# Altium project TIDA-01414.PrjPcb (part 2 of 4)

## Sheet TIDA-01414_UpChannel.SchDoc: Main Schematic
size 538 x 342 mm; Date: Not shown in title block; ApprovedBy: Not shown in title block; CheckedBy: Not shown in title block; Author: Not shown in title block; CompanyName: Not shown in title block; DrawnBy: LDN; Engineer: Not shown in title block; Organization: Not shown in title block; Address1: Not shown in title block; Address2: Not shown in title block; Address3: Not shown in title block; Address4: Not shown in title block; DocumentNumber: 4; Revision: Use project parameter SCH_Rev; SheetNumber: 4; SheetTotal: 12; PageSetup: Record=PageOptions¦CenterHorizontal=True¦CenterVertical=True¦PrintScale=1.00¦XCorrection=1.00¦YCorrection=1.00¦PrintKind=0¦BorderSize=5000000¦LeftOffset=0¦BottomOffset=0¦Orientation=2¦PaperLength=1000¦PaperWidth=1000¦Scale=100¦PaperSource=15¦PrintQuality=600¦MediaType=1¦DitherType=10¦PaperKind=Letter¦PrintScaleMode=1
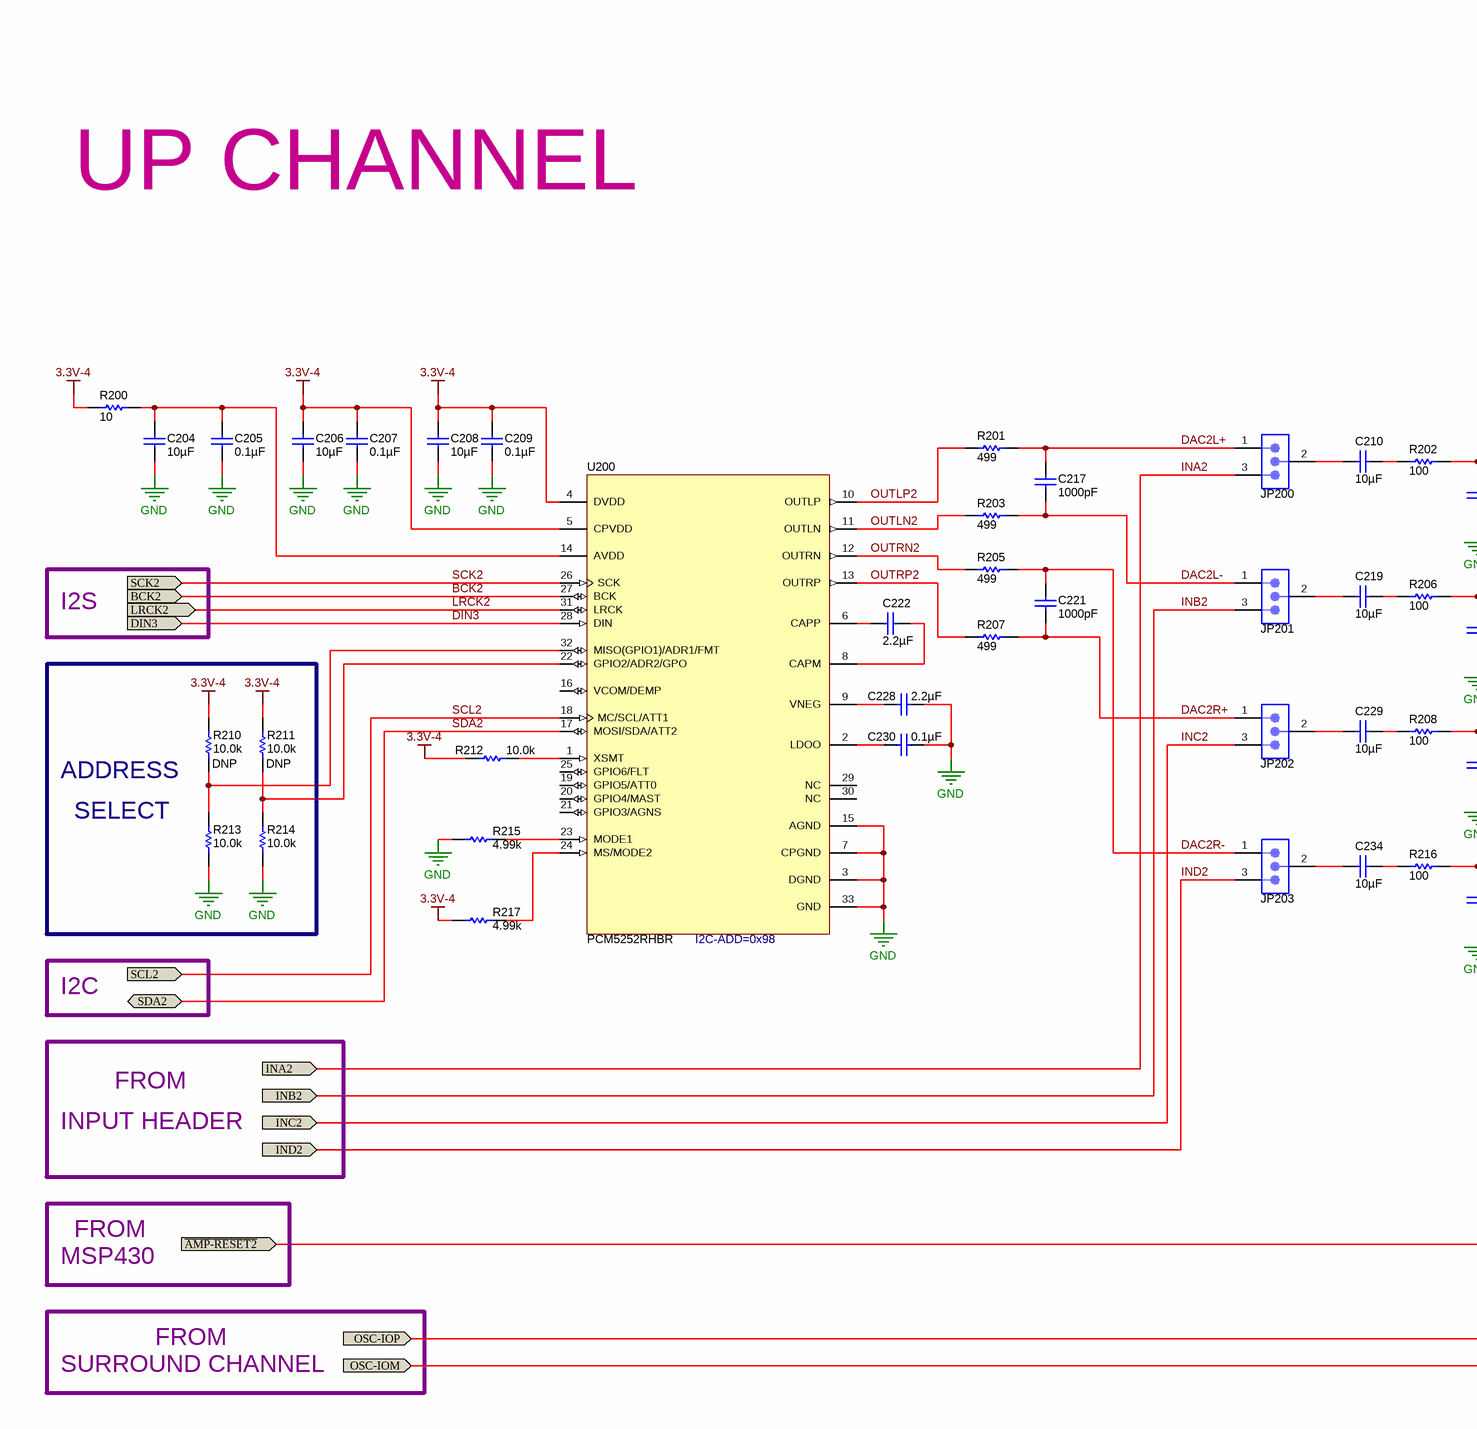
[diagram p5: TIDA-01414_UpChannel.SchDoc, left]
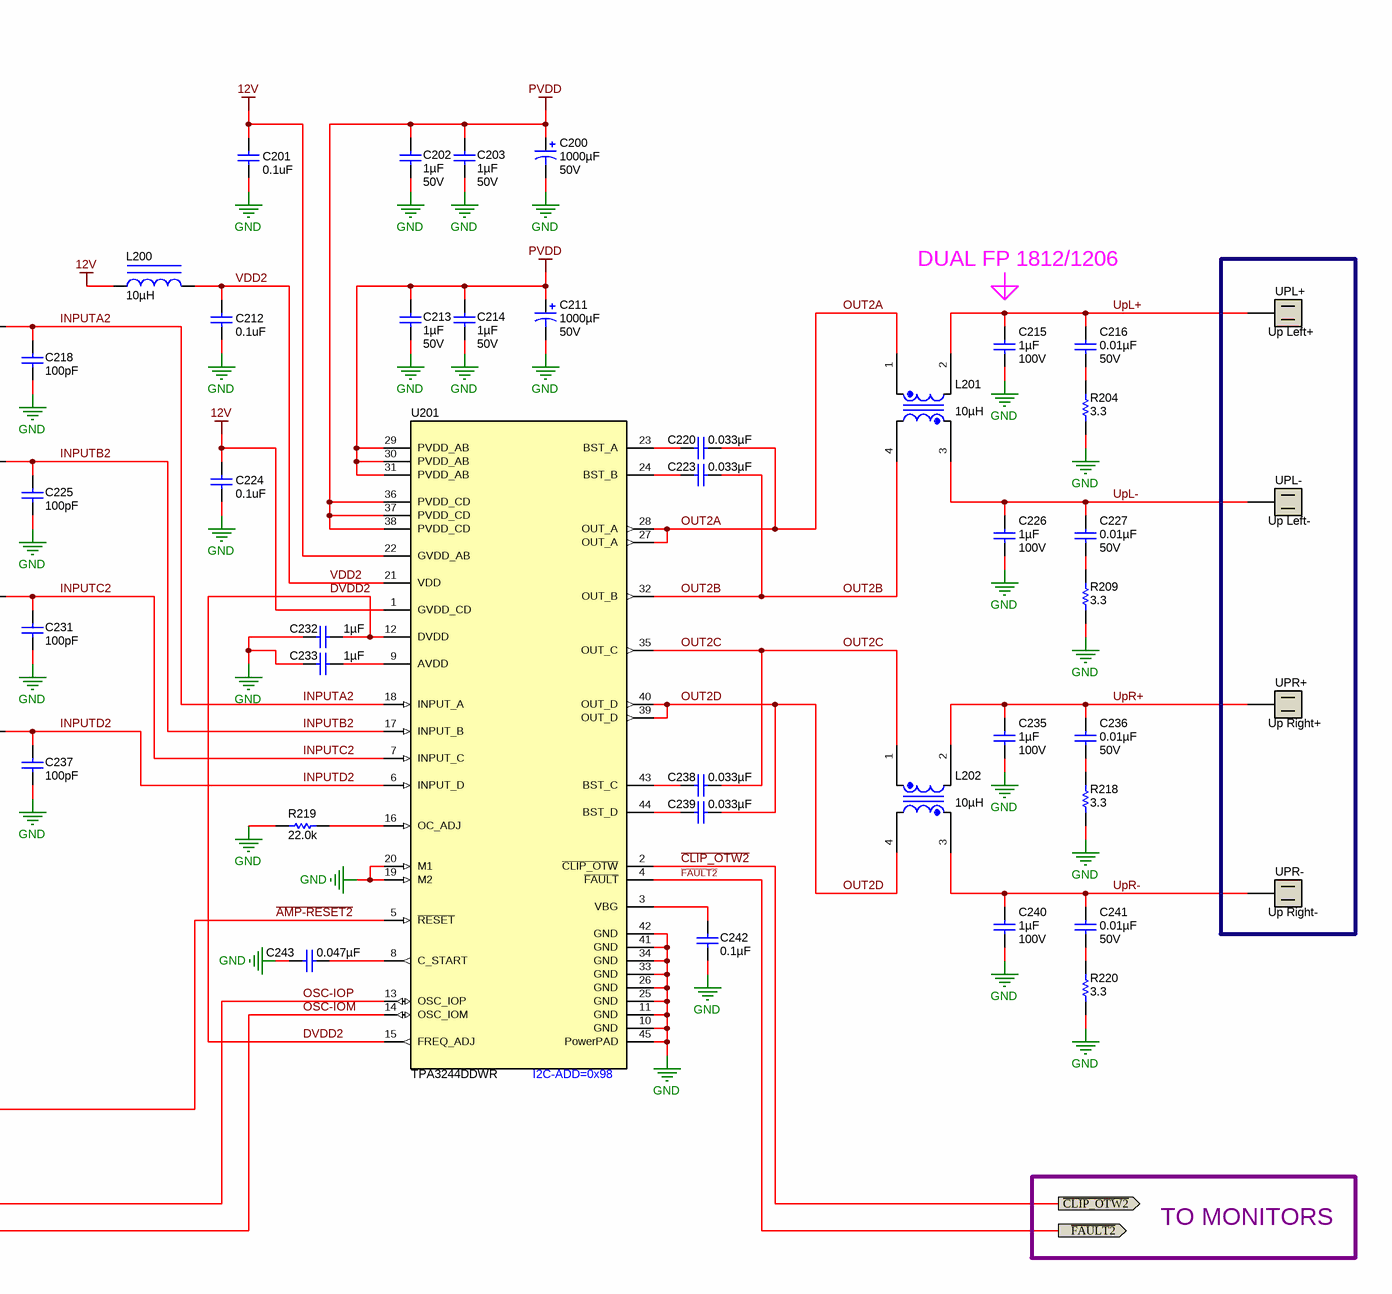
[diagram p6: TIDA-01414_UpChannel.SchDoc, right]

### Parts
C200  ValueDisplayed: 1000µF  Value2: 50V  [SM_RADIAL_J16]  (hidden comment: +)
C201  value 0.1uF  [0603L]  (hidden comment: C0603C104K5RACTU)
C202  ValueDisplayed: 1µF  Value2: 50V  [1206L]  (hidden comment: GRM31MR71H105KA88L)
C203  ValueDisplayed: 1µF  Value2: 50V  [1206L]  (hidden comment: GRM31MR71H105KA88L)
C204  ValueDisplayed: 10µF  [0603L]  (hidden comment: GRM188R61A106ME69D)
C205  ValueDisplayed: 0.1µF  [0402L]  (hidden comment: GRM155R71A104KA01D)
C206  ValueDisplayed: 10µF  [0603L]  (hidden comment: GRM188R61A106ME69D)
C207  ValueDisplayed: 0.1µF  [0402L]  (hidden comment: GRM155R71A104KA01D)
C208  ValueDisplayed: 10µF  [0603L]  (hidden comment: GRM188R61A106ME69D)
C209  ValueDisplayed: 0.1µF  [0402L]  (hidden comment: GRM155R71A104KA01D)
C210  ValueDisplayed: 10µF  [1206_180]  (hidden comment: GRM31CR71C106KAC7L)
C211  ValueDisplayed: 1000µF  Value2: 50V  [SM_RADIAL_J16]  (hidden comment: +)
C212  value 0.1uF  [0603L]  (hidden comment: C0603C104K5RACTU)
C213  ValueDisplayed: 1µF  Value2: 50V  [1206L]  (hidden comment: GRM31MR71H105KA88L)
C214  ValueDisplayed: 1µF  Value2: 50V  [1206L]  (hidden comment: GRM31MR71H105KA88L)
C215  ValueDisplayed: 1µF  Value2: 100V  [1210_220]  (hidden comment: C3225X7R2A105K200AA)
C216  ValueDisplayed: 0.01µF  Value2: 50V  [0603L]  (hidden comment: C0603C103K5RACTU)
C217  ValueDisplayed: 1000pF  [0402L]  (hidden comment: GRM1555C1H102JA01D)
C218  ValueDisplayed: 100pF  [0603L]  (hidden comment: GRM1885C1H101JA01D)
C219  ValueDisplayed: 10µF  [1206_180]  (hidden comment: GRM31CR71C106KAC7L)
C220  ValueDisplayed: 0.033µF  [0603L]  (hidden comment: GRM188R71E333KA01D)
C221  ValueDisplayed: 1000pF  [0402L]  (hidden comment: GRM1555C1H102JA01D)
C222  ValueDisplayed: 2.2µF  [0402L]  (hidden comment: C1005X5R1A225K050BC)
C223  ValueDisplayed: 0.033µF  [0603L]  (hidden comment: GRM188R71E333KA01D)
C224  value 0.1uF  [0603L]  (hidden comment: C0603C104K5RACTU)
C225  ValueDisplayed: 100pF  [0603L]  (hidden comment: GRM1885C1H101JA01D)
C226  ValueDisplayed: 1µF  Value2: 100V  [1210_220]  (hidden comment: C3225X7R2A105K200AA)
C227  ValueDisplayed: 0.01µF  Value2: 50V  [0603L]  (hidden comment: C0603C103K5RACTU)
C228  ValueDisplayed: 2.2µF  [0402L]  (hidden comment: C1005X5R1A225K050BC)
C229  ValueDisplayed: 10µF  [1206_180]  (hidden comment: GRM31CR71C106KAC7L)
C230  ValueDisplayed: 0.1µF  [0402L]  (hidden comment: GRM155R71A104KA01D)
C231  ValueDisplayed: 100pF  [0603L]  (hidden comment: GRM1885C1H101JA01D)
C232  ValueDisplayed: 1µF  [0603L]  (hidden comment: GRM188R71C105KA12D)
C233  ValueDisplayed: 1µF  [0603L]  (hidden comment: GRM188R71C105KA12D)
C234  ValueDisplayed: 10µF  [1206_180]  (hidden comment: GRM31CR71C106KAC7L)
C235  ValueDisplayed: 1µF  Value2: 100V  [1210_220]  (hidden comment: C3225X7R2A105K200AA)
C236  ValueDisplayed: 0.01µF  Value2: 50V  [0603L]  (hidden comment: C0603C103K5RACTU)
C237  ValueDisplayed: 100pF  [0603L]  (hidden comment: GRM1885C1H101JA01D)
C238  ValueDisplayed: 0.033µF  [0603L]  (hidden comment: GRM188R71E333KA01D)
C239  ValueDisplayed: 0.033µF  [0603L]  (hidden comment: GRM188R71E333KA01D)
C240  ValueDisplayed: 1µF  Value2: 100V  [1210_220]  (hidden comment: C3225X7R2A105K200AA)
C241  ValueDisplayed: 0.01µF  Value2: 50V  [0603L]  (hidden comment: C0603C103K5RACTU)
C242  ValueDisplayed: 0.1µF  [0603L]  (hidden comment: C0603C104K5RACTU)
C243  ValueDisplayed: 0.047µF  [0603L]  (hidden comment: GRM188R71H473KA61D)
JP200  PBC03SAAN  [PBC03SAAN]  (value not drawn)
JP201  PBC03SAAN  [PBC03SAAN]  (value not drawn)
JP202  PBC03SAAN  [PBC03SAAN]  (value not drawn)
JP203  PBC03SAAN  [PBC03SAAN]  (value not drawn)
L200  ValueDisplayed: 10µH  [0603L]  (hidden comment: GLFR1608T100M-LR)
L201  ValueDisplayed: 10µH  [Coilcraft_RA7231-ALB]  (hidden comment: UA8014-ALD)
L202  ValueDisplayed: 10µH  [Coilcraft_RA7231-ALB]  (hidden comment: UA8014-ALD)
R200  ValueDisplayed: 10  [0603L]  (hidden comment: CRCW060310R0JNEA)
R201  ValueDisplayed: 499  [0603L]  (hidden comment: CRCW0603499RFKEA)
R202  ValueDisplayed: 100  [0603L]  (hidden comment: CRCW0603100RFKEA)
R203  ValueDisplayed: 499  [0603L]  (hidden comment: CRCW0603499RFKEA)
R204  ValueDisplayed: 3.3  [0603L]  (hidden comment: CRCW06033R30JNEA)
R205  ValueDisplayed: 499  [0603L]  (hidden comment: CRCW0603499RFKEA)
R206  ValueDisplayed: 100  [0603L]  (hidden comment: CRCW0603100RFKEA)
R207  ValueDisplayed: 499  [0603L]  (hidden comment: CRCW0603499RFKEA)
R208  ValueDisplayed: 100  [0603L]  (hidden comment: CRCW0603100RFKEA)
R209  ValueDisplayed: 3.3  [0603L]  (hidden comment: CRCW06033R30JNEA)
R210  DNP  ValueDisplayed: 10.0k  [0402L]
R211  DNP  ValueDisplayed: 10.0k  [0402L]
R212  ValueDisplayed: 10.0k  [0402L]  (hidden comment: ERJ-2RKF1002X)
R213  ValueDisplayed: 10.0k  [0402L]  (hidden comment: ERJ-2RKF1002X)
R214  ValueDisplayed: 10.0k  [0402L]  (hidden comment: ERJ-2RKF1002X)
R215  ValueDisplayed: 4.99k  [0402L]  (hidden comment: CRCW04024K99FKED)
R216  ValueDisplayed: 100  [0603L]  (hidden comment: CRCW0603100RFKEA)
R217  ValueDisplayed: 4.99k  [0402L]  (hidden comment: CRCW04024K99FKED)
R218  ValueDisplayed: 3.3  [0603L]  (hidden comment: CRCW06033R30JNEA)
R219  ValueDisplayed: 22.0k  [0603L]  (hidden comment: RC0603FR-0722KL)
R220  ValueDisplayed: 3.3  [0603L]  (hidden comment: CRCW06033R30JNEA)
U200  PCM5252RHBR  [RHB0032E]
U201  TPA3244DDWR  [DDW0044D_N]
UPL+  Up Left+  [TEC-SpadeLug_63066-1]
UPL-  Up Left-  [TEC-SpadeLug_63066-1]
UPR+  Up Right+  [TEC-SpadeLug_63066-1]
UPR-  Up Right-  [TEC-SpadeLug_63066-1]

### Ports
BCK2 (in), DIN3 (in), INA2 (in), INB2 (in), INC2 (in), IND2 (in), LRCK2 (in), OSC-IOM (in), OSC-IOP (in), SCK2 (in), SCL2 (in), SDA2 (bidir), ~{AMP-RESET2} (in), ~{CLIP_OTW2} (out), ~{FAULT2} (out)

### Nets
3.3V-4: C206.1 C207.1 C208.1 C209.1 R200.1 R210.2 R211.2 R212.1 R217.2 U200.4(DVDD) U200.5(CPVDD)
12V: C201.1 C224.1 L200.1 U201.1(GVDD_CD) U201.22(GVDD_AB)
GND: C200.2(-) C201.2 C202.1 C203.1 C204.2 C205.2 C206.2 C207.2 C208.2 C209.2 C211.2(-) C212.2 C213.1 C214.1 C215.2 C218.2 C224.2 C225.2 C226.2 C228.2 C230.2 C231.2 C232.1 C233.1 C235.2 C237.2 C240.2 C242.1 C243.2 R204.1 R209.1 R213.1 R214.1 R215.2 R218.1 R219.1 R220.1 U200.3(DGND) U200.7(CPGND) U200.15(AGND) U200.33(GND) U201.10(GND) U201.11(GND) U201.19(M2) U201.20(M1) U201.25(GND) U201.26(GND) U201.33(GND) U201.34(GND) U201.41(GND) U201.42(GND) U201.45(PowerPAD)
PVDD: C200.1(+) C202.2 C203.2 C211.1(+) C213.2 C214.2 U201.29(PVDD_AB) U201.30(PVDD_AB) U201.31(PVDD_AB) U201.36(PVDD_CD) U201.37(PVDD_CD) U201.38(PVDD_CD)
~{AMP-RESET2}: U201.5(~{RESET}) ; port ~{AMP-RESET2}
~{CLIP_OTW2}: U201.2(~{CLIP_OTW}) ; port ~{CLIP_OTW2}
~{FAULT2}: U201.4(~{FAULT}) ; port ~{FAULT2}
BCK2: U200.27(BCK) ; port BCK2
DAC2L+: C217.1 JP200.1 R201.2
DAC2L-: C217.2 JP201.1 R203.2
DAC2R+: C221.2 JP202.1 R207.2
DAC2R-: C221.1 JP203.1 R205.2
DIN3: U200.28(DIN) ; port DIN3
DVDD2: C232.2 U201.12(DVDD) U201.15(FREQ_ADJ)
INA2: JP200.3 ; port INA2
INB2: JP201.3 ; port INB2
INC2: JP202.3 ; port INC2
IND2: JP203.3 ; port IND2
INPUTA2: C218.1 R202.2 U201.18(INPUT_A)
INPUTB2: C225.1 R206.2 U201.17(INPUT_B)
INPUTC2: C231.1 R208.2 U201.7(INPUT_C)
INPUTD2: C237.1 R216.2 U201.6(INPUT_D)
LRCK2: U200.31(LRCK) ; port LRCK2
OSC-IOM: U201.14(OSC_IOM) ; port OSC-IOM
OSC-IOP: U201.13(OSC_IOP) ; port OSC-IOP
OUT2A: C220.1 L201.1 U201.27(OUT_A) U201.28(OUT_A)
OUT2B: C223.1 L201.4 U201.32(OUT_B)
OUT2C: C238.1 L202.1 U201.35(OUT_C)
OUT2D: C239.1 L202.4 U201.39(OUT_D) U201.40(OUT_D)
OUTLN2: R203.1 U200.11(OUTLN)
OUTLP2: R201.1 U200.10(OUTLP)
OUTRN2: R205.1 U200.12(OUTRN)
OUTRP2: R207.1 U200.13(OUTRP)
SCK2: U200.26(SCK) ; port SCK2
SCL2: U200.18(MC/SCL/ATT1) ; port SCL2
SDA2: U200.17(MOSI/SDA/ATT2) ; port SDA2
UpL+: C215.1 C216.1 L201.2 UPL+.1
UpL-: C226.1 C227.1 L201.3 UPL-.1
UpR+: C235.1 C236.1 L202.2 UPR+.1
UpR-: C240.1 C241.1 L202.3 UPR-.1
VDD2: C212.1 L200.2 U201.21(VDD)
NetC204_1: C204.1 C205.1 R200.2 U200.14(AVDD)
NetC210_1: C210.1 JP200.2
NetC210_2: C210.2 R202.1
NetC216_2: C216.2 R204.2
NetC219_1: C219.1 JP201.2
NetC219_2: C219.2 R206.1
NetC220_2: C220.2 U201.23(BST_A)
NetC222_1: C222.1 U200.6(CAPP)
NetC222_2: C222.2 U200.8(CAPM)
NetC223_2: C223.2 U201.24(BST_B)
NetC227_2: C227.2 R209.2
NetC228_1: C228.1 U200.9(VNEG)
NetC229_1: C229.1 JP202.2
NetC229_2: C229.2 R208.1
NetC230_1: C230.1 U200.2(LDOO)
NetC233_2: C233.2 U201.9(AVDD)
NetC234_1: C234.1 JP203.2
NetC234_2: C234.2 R216.1
NetC236_2: C236.2 R218.2
NetC238_2: C238.2 U201.43(BST_C)
NetC239_2: C239.2 U201.44(BST_D)
NetC241_2: C241.2 R220.2
NetC242_2: C242.2 U201.3(VBG)
NetC243_1: C243.1 U201.8(C_START)
NetR210_1: R210.1 R213.2 U200.32(MISO(GPIO1)/ADR1/FMT)
NetR211_1: R211.1 R214.2 U200.22(GPIO2/ADR2/GPO)
NetR212_2: R212.2 U200.1(XSMT)
NetR215_1: R215.1 U200.23(MODE1)
NetR217_1: R217.1 U200.24(MS/MODE2)
NetR219_2: R219.2 U201.16(OC_ADJ)

Not connected (* = marked no-connect by the designer): U200 16(VCOM/DEMP) 19(GPIO5/ATT0) 20(GPIO4/MAST) 21(GPIO3/AGNS) 25(GPIO6/FLT) 29(NC) 30(NC)

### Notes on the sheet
- UP CHANNEL
- DUAL FP 1812/1206
- I2S
- ADDRESS
- SELECT
- (near U200) I2C-ADD=0x98
- I2C
- FROM
- INPUT HEADER
- (near U201) I2C-ADD=0x98
- MSP430
- TO MONITORS
- SURROUND CHANNEL

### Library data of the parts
C200 C211 = EEV-FK1H102M: CAP, AL, 1000 µF, 50 V, +/- 20%, 0.073 ohm, AEC-Q200 Grade 2, SMD; Manufacturer: Panasonic; Polarized: Y; CompType: Capacitor; Value: 1000uF; U/M: EA; Cap_F: 0.001; Tolerance_%: 20; VDC_V: 50; ESR_ohm: 0.073; IRMS_A: 1.61; TaMin_C: -55; TaMax_C: 105; Cap_Case: J16; SizeAreaWB_mm2: 399; SizeArea_mm2: 323; SizeX_mm: 19; SizeY_mm: 17; SizeZ_mm: 16.5; AEC Category: Q200; AEC Grade: 2
C201 C212 C224 = C0603C104K5RACTU: CAP, CERM, 0.1 µF, 50 V, +/- 10%, X7R, 0603; Manufacturer: Kemet; Polarized: N; CompType: Capacitor; ValueDisplayed: 0.1µF; U/M: EA; Cap_F: 0.0000001; Tolerance_%: 10; Value1: Unknown; VDC_V: 50; Value2: 50V; TaMin_C: -55; TaMax_C: 125; Cap_Case: 0603; AEC Category: Q200
C202 C203 C213 C214 = GRM31MR71H105KA88L: CAP, CERM, 1 µF, 50 V, +/- 10%, X7R, 1206; Manufacturer: MuRata; Polarized: N; CompType: Capacitor; Value: 1uF; U/M: EA; Cap_F: 0.000001; Tolerance_%: 10; Value1: Unknown; VDC_V: 50; TaMin_C: -55; TaMax_C: 125; Cap_Case: 1206; AEC Category: Q200
C204 C206 C208 = GRM188R61A106ME69D: CAP, CERM, 10 µF, 10 V, +/- 20%, X5R, 0603; Manufacturer: MuRata; Polarized: N; CompType: Capacitor; Value: 10uF; U/M: EA; Cap_F: 0.00001; Tolerance_%: 20; Value1: Unknown; VDC_V: 10; Value2: 10V; TaMin_C: -55; TaMax_C: 85; Cap_Case: 0603; AEC Category: Q200
C205 C207 C209 C230 = GRM155R71A104KA01D: CAP, CERM, 0.1 µF, 10 V, +/- 10%, X7R, 0402; Manufacturer: MuRata; Polarized: N; CompType: Capacitor; Value: 0.1uF; U/M: EA; Cap_F: 0.0000001; Tolerance_%: 10; Value1: Unknown; Value2: 10V; TaMin_C: -55; TaMax_C: 125; Cap_Case: 0402; AEC Category: Q200
C210 C219 C229 C234 = GRM31CR71C106KAC7L: CAP, CERM, 10 µF, 16 V, +/- 10%, X7R, 1206; Manufacturer: MuRata; Polarized: N; CompType: Capacitor; Value: 10uF; U/M: EA; Cap_F: 0.00001; Tolerance_%: 10; Value1: Unknown; VDC_V: 16; Value2: 16V; TaMin_C: -55; TaMax_C: 125; Cap_Case: 1206; AEC Category: Q200; SizeArea_mm2: 5.12; SizeAreaWB_mm2: 10.92; SizeX_mm: 3.2; SizeY_mm: 1.6; SizeZ_mm: 1.8
C215 C226 C235 C240 = C3225X7R2A105K200AA: CAP, CERM, 1 µF, 100 V, +/- 10%, X7R, 1210; Manufacturer: TDK; Polarized: N; CompType: Capacitor; Value: 1uF; U/M: EA; Cap_F: 0.000001; Tolerance_%: 10; Value1: 0.004956 ohm; VDC_V: 100; ESR_ohm: 0.004956; IRMS_A: 3.30731; TaMin_C: -55; TaMax_C: 125; AEC Category: Q200; SizeArea_mm2: 8; SizeAreaWB_mm2: 14.7; SizeX_mm: 3.2; SizeY_mm: 2.5; SizeZ_mm: 2.2
C216 C227 C236 C241 = C0603C103K5RACTU: CAP, CERM, 0.01 µF, 50 V, +/- 10%, X7R, 0603; Manufacturer: Kemet; Polarized: N; CompType: Capacitor; Value: 0.01uF; U/M: EA; Cap_F: 0.00000001; Tolerance_%: 10; Value1: Unknown; VDC_V: 50; TaMin_C: -55; TaMax_C: 125; Cap_Case: 0603; AEC Category: Q200
C217 C221 = GRM1555C1H102JA01D: CAP, CERM, 1000 pF, 50 V, +/- 5%, C0G/NP0, 0402; Manufacturer: MuRata; Polarized: N; CompType: Capacitor; Value: 1000pF; U/M: EA; Cap_F: 0.000000001; Tolerance_%: 5; Value1: Unknown; VDC_V: 50; Value2: 50V; TaMin_C: -55; TaMax_C: 125; Cap_Case: 0402; AEC Category: Q200
C218 C225 C231 C237 = GRM1885C1H101JA01D: CAP, CERM, 100 pF, 50 V, +/- 5%, C0G/NP0, 0603; Manufacturer: MuRata; Polarized: N; CompType: Capacitor; Value: 100pF; U/M: EA; Cap_F: 0.0000000001; Tolerance_%: 5; Value1: Unknown; VDC_V: 50; Value2: 50V; TaMin_C: -55; TaMax_C: 125; Cap_Case: 0603; AEC Category: Q200
C220 C223 C238 C239 = GRM188R71E333KA01D: CAP, CERM, 0.033 µF, 25 V, +/- 10%, X7R, 0603; Manufacturer: MuRata; Polarized: N; CompType: Capacitor; Value: 0.033uF; U/M: EA; Cap_F: 0.000000033; Tolerance_%: 10; Value1: Unknown; VDC_V: 25; Value2: 25V; TaMin_C: -55; TaMax_C: 125; Cap_Case: 0603; AEC Category: Q200
C222 C228 = C1005X5R1A225K050BC: CAP, CERM, 2.2 µF, 10 V, +/- 10%, X5R, 0402; Manufacturer: TDK; Polarized: N; CompType: Capacitor; Value: 2.2uF; U/M: EA; Cap_F: 0.0000022; Tolerance_%: 10; Value1: Unknown; Value2: 10V; TaMin_C: -55; TaMax_C: 85; Cap_Case: 0402; AEC Category: Q200
C232 C233 = GRM188R71C105KA12D: CAP, CERM, 1 µF, 16 V, +/- 10%, X7R, 0603; Manufacturer: MuRata; Polarized: N; CompType: Capacitor; Value: 1uF; U/M: EA; Cap_F: 0.000001; Tolerance_%: 10; ESR_ohm: 0.011; Value1: 0.011 ohm; VDC_V: 16; Value2: 16V; TaMin_C: -55; TaMax_C: 125; Cap_Case: 0603; AEC Category: Q200
C242 = C0603C104K5RACTU: CAP, CERM, 0.1 µF, 50 V, +/- 10%, X7R, 0603; Manufacturer: Kemet; Polarized: N; CompType: Capacitor; Value: 0.1uF; U/M: EA; Cap_F: 0.0000001; Tolerance_%: 10; Value1: Unknown; VDC_V: 50; Value2: 50V; TaMin_C: -55; TaMax_C: 125; Cap_Case: 0603; AEC Category: Q200
C243 = GRM188R71H473KA61D: CAP, CERM, 0.047 µF, 50 V, +/- 10%, X7R, 0603; Manufacturer: MuRata; Polarized: N; CompType: Capacitor; Value: 0.047uF; U/M: EA; Cap_F: 0.000000047; Tolerance_%: 10; Value1: Unknown; VDC_V: 50; Value2: 50V; TaMin_C: -55; TaMax_C: 125; Cap_Case: 0603; AEC Category: Q200
JP200-JP203 = SIP3-90_PBC03SAAN: Header, 100mil, 3x1, Gold, TH; Manufacturer: Sullins Connector Solutions; Value: 1x3; U/M: EA
L200 = GLFR1608T100M-LR: Inductor, Wirewound, 10 µH, 0.08 A, 0.36 ohm, SMD; Manufacturer: TDK; Value: 10uH; Value2: 0.08A; Ind_H: 10.0E-6; Imax_A: 0.08; Irms: 0.4A @ 20C rise; Isat: 0.08A @ 10% inductance drop; DCR_ohm: 0.36; AEC Category: Q200; AEC Qualified: N
L201 L202 = UA8014-ALD: Coupled inductor, 10 µH, 6.6 A, SMD; Manufacturer: Coilcraft; SymbolCreator: a0799628; Value: 10uH; Ind_H: 1.0E-7
R200 = CRCW060310R0JNEA: RES, 10, 5%, 0.1 W, 0603; Manufacturer: Vishay-Dale; CompType: Resistor; Value: 10; Value_Code: 10R0; Tolerance_%: 5; Power_W: 0.1; Value2: 0.1W; VDC_V: 75; TempCo: 200 ppm/C; EIA_Code: E24; U/M: EA; AEC Category: Q200
R201 R203 R205 R207 = CRCW0603499RFKEA: RES, 499, 1%, 0.1 W, 0603; Manufacturer: Vishay-Dale; CompType: Resistor; Value: 499; Value_Code: 499R; Tolerance_%: 1; Power_W: 0.1; Value2: 0.1W; VDC_V: 75; TempCo: 100 ppm/C; EIA_Code: E96; U/M: EA; AEC Category: Q200
R202 R206 R208 R216 = CRCW0603100RFKEA: RES, 100, 1%, 0.1 W, 0603; Manufacturer: Vishay-Dale; CompType: Resistor; Value: 100; Value_Code: 100R; Tolerance_%: 1; Power_W: 0.1; Value2: 0.1W; VDC_V: 75; TempCo: 100 ppm/C; EIA_Code: E96; U/M: EA; AEC Category: Q200
R204 R209 R218 R220 = CRCW06033R30JNEA: RES, 3.3, 5%, 0.1 W, 0603; Manufacturer: Vishay-Dale; CompType: Resistor; Value: 3.3; Value_Code: 3R30; Tolerance_%: 5; Power_W: 0.1; Value2: 0.1W; VDC_V: 75; TempCo: 200 ppm/C; EIA_Code: E24; U/M: EA; AEC Category: Q200
R210-R214 = ERJ-2RKF1002X: RES, 10.0 k, 1%, 0.1 W, 0402; Manufacturer: Panasonic; CompType: Resistor; Value: 10.0k; Res_ohm: 10000; Value_Code: 10k0; Tolerance_%: 1; Power_W: 0.1; Value2: 0.1W; VDC_V: 50; TempCo: 100 ppm/C; EIA_Code: E96; U/M: EA; AEC Category: Q200
R215 R217 = CRCW04024K99FKED: RES, 4.99 k, 1%, 0.063 W, 0402; Manufacturer: Vishay-Dale; CompType: Resistor; Value: 4.99k; Res_ohm: 4990; Value_Code: 4k99; Tolerance_%: 1; Power_W: 0.063; Value2: 0.063W; VDC_V: 50; TempCo: 100 ppm/C; EIA_Code: E96; U/M: EA; AEC Category: Q200
R219 = RC0603FR-0722KL: RES, 22.0 k, 1%, 0.1 W, 0603; Manufacturer: Yageo America; CompType: Resistor; Value: 22.0k; Res_ohm: 22000; Value_Code: 22k0; Tolerance_%: 1; Power_W: 0.1; Value2: 0.1W; VDC_V: 150; TempCo: 200 ppm/C; U/M: EA; AEC Category: Q200
U200 = PCM5252RHBR: 4.2VRMS DirectPath™, 114dB Audio Stereo Differential-Output DAC with 32-bit, 384kHz PCM Interface, RHB0032E; Alternate PartNumber: PCM5252RHBT; Manufacturer: Texas Instruments; SymbolCreator: Altium; CompType: IC; U/M: EA
U201 = TPA3244DDWR: 40-W Stereo, 100-W peak PurePath™ Ultra-HD Pad Down Class-D Amplifier, DDW0044D; Manufacturer: Texas Instruments; SymbolCreator: Altium; SizeArea_mm2: 113.4; SizeAreaWB_mm2: 161.6; SizeX_mm: 8.1; SizeY_mm: 14; SizeZ_mm: 1.2; CompType: IC; U/M: EA
UPL+ UPL- UPR+ UPR- = 63066-1: PC Quick-Fit 0.250 Tab, Vertical, TH; Manufacturer: TE Connectivity; SymbolCreator: x0221032; CompType: Quick-Fit Tab; Gender: Male; Row_Count: 1; ContactFinish: Tin

## Sheet TIDA-01414_FrontRightChannel.SchDoc: Main Schematic
size 538 x 342 mm; Date: Not shown in title block; ApprovedBy: Not shown in title block; CheckedBy: Not shown in title block; Author: Not shown in title block; CompanyName: Not shown in title block; DrawnBy: LDN; Engineer: Not shown in title block; Organization: Not shown in title block; Address1: Not shown in title block; Address2: Not shown in title block; Address3: Not shown in title block; Address4: Not shown in title block; DocumentNumber: 5; Revision: Use project parameter SCH_Rev; SheetNumber: 5; SheetTotal: 12; PageSetup: Record=PageOptions¦CenterHorizontal=True¦CenterVertical=True¦PrintScale=1.00¦XCorrection=1.00¦YCorrection=1.00¦PrintKind=0¦BorderSize=5000000¦LeftOffset=0¦BottomOffset=0¦Orientation=2¦PaperLength=1000¦PaperWidth=1000¦Scale=100¦PaperSource=15¦PrintQuality=600¦MediaType=1¦DitherType=10¦PaperKind=Letter¦PrintScaleMode=1
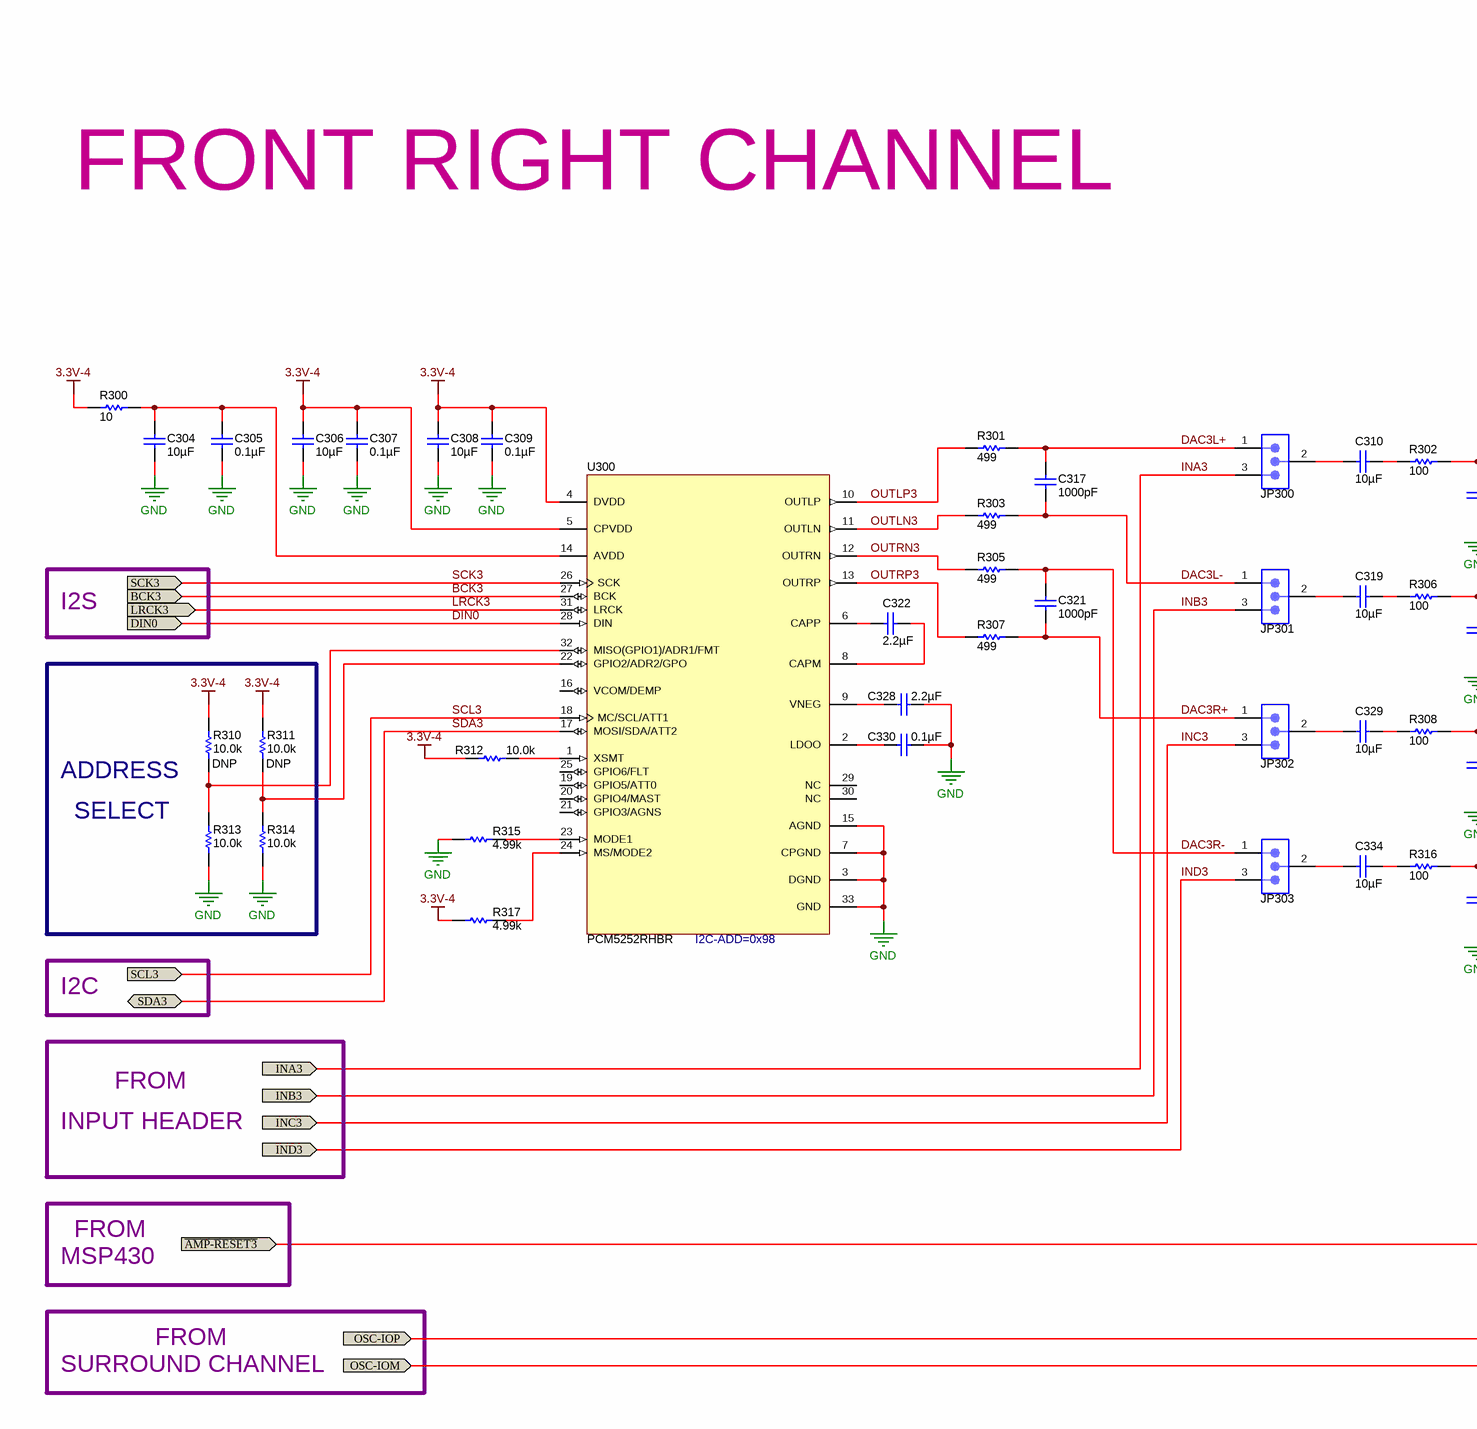
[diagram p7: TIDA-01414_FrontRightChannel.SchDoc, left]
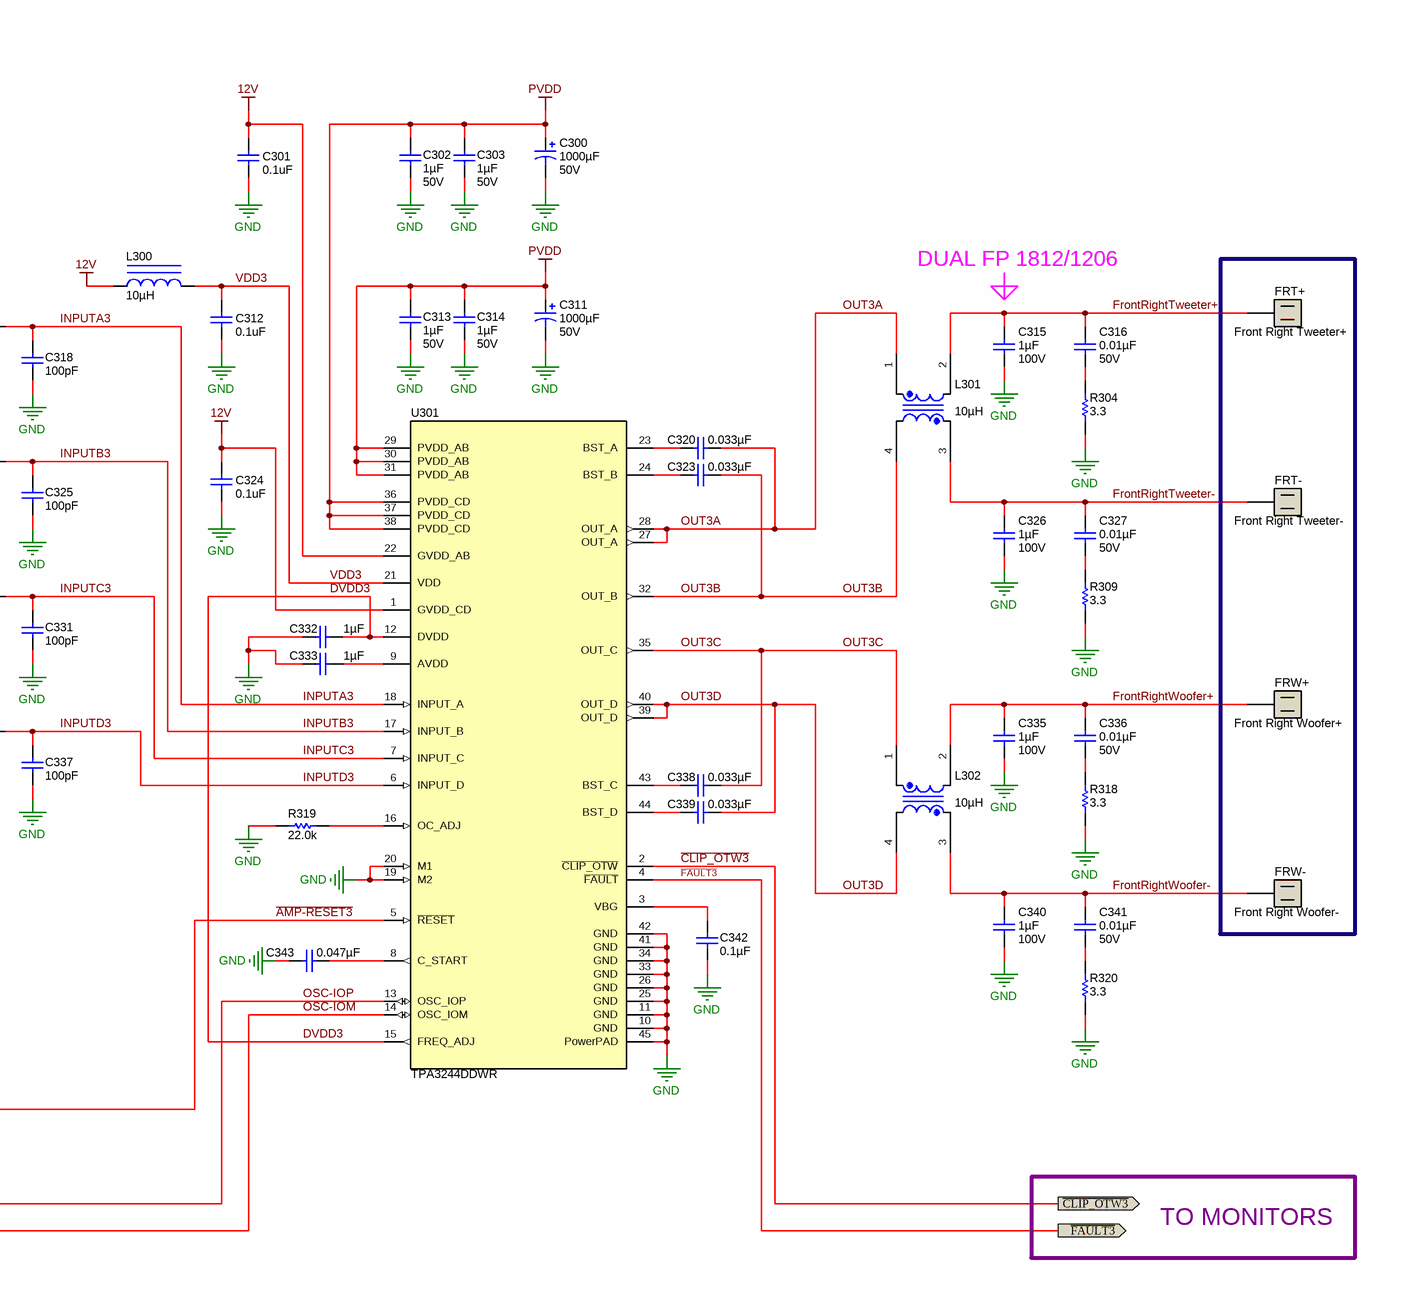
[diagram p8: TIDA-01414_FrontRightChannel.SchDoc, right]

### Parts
C300  ValueDisplayed: 1000µF  Value2: 50V  [SM_RADIAL_J16]  (hidden comment: +)
C301  value 0.1uF  [0603L]  (hidden comment: C0603C104K5RACTU)
C302  ValueDisplayed: 1µF  Value2: 50V  [1206L]  (hidden comment: GRM31MR71H105KA88L)
C303  ValueDisplayed: 1µF  Value2: 50V  [1206L]  (hidden comment: GRM31MR71H105KA88L)
C304  ValueDisplayed: 10µF  [0603L]  (hidden comment: GRM188R61A106ME69D)
C305  ValueDisplayed: 0.1µF  [0402L]  (hidden comment: GRM155R71A104KA01D)
C306  ValueDisplayed: 10µF  [0603L]  (hidden comment: GRM188R61A106ME69D)
C307  ValueDisplayed: 0.1µF  [0402L]  (hidden comment: GRM155R71A104KA01D)
C308  ValueDisplayed: 10µF  [0603L]  (hidden comment: GRM188R61A106ME69D)
C309  ValueDisplayed: 0.1µF  [0402L]  (hidden comment: GRM155R71A104KA01D)
C310  ValueDisplayed: 10µF  [1206_180]  (hidden comment: GRM31CR71C106KAC7L)
C311  ValueDisplayed: 1000µF  Value2: 50V  [SM_RADIAL_J16]  (hidden comment: +)
C312  value 0.1uF  [0603L]  (hidden comment: C0603C104K5RACTU)
C313  ValueDisplayed: 1µF  Value2: 50V  [1206L]  (hidden comment: GRM31MR71H105KA88L)
C314  ValueDisplayed: 1µF  Value2: 50V  [1206L]  (hidden comment: GRM31MR71H105KA88L)
C315  ValueDisplayed: 1µF  Value2: 100V  [1210_220]  (hidden comment: C3225X7R2A105K200AA)
C316  ValueDisplayed: 0.01µF  Value2: 50V  [0603L]  (hidden comment: C0603C103K5RACTU)
C317  ValueDisplayed: 1000pF  [0402L]  (hidden comment: GRM1555C1H102JA01D)
C318  ValueDisplayed: 100pF  [0603L]  (hidden comment: GRM1885C1H101JA01D)
C319  ValueDisplayed: 10µF  [1206_180]  (hidden comment: GRM31CR71C106KAC7L)
C320  ValueDisplayed: 0.033µF  [0603L]  (hidden comment: GRM188R71E333KA01D)
C321  ValueDisplayed: 1000pF  [0402L]  (hidden comment: GRM1555C1H102JA01D)
C322  ValueDisplayed: 2.2µF  [0402L]  (hidden comment: C1005X5R1A225K050BC)
C323  ValueDisplayed: 0.033µF  [0603L]  (hidden comment: GRM188R71E333KA01D)
C324  value 0.1uF  [0603L]  (hidden comment: C0603C104K5RACTU)
C325  ValueDisplayed: 100pF  [0603L]  (hidden comment: GRM1885C1H101JA01D)
C326  ValueDisplayed: 1µF  Value2: 100V  [1210_220]  (hidden comment: C3225X7R2A105K200AA)
C327  ValueDisplayed: 0.01µF  Value2: 50V  [0603L]  (hidden comment: C0603C103K5RACTU)
C328  ValueDisplayed: 2.2µF  [0402L]  (hidden comment: C1005X5R1A225K050BC)
C329  ValueDisplayed: 10µF  [1206_180]  (hidden comment: GRM31CR71C106KAC7L)
C330  ValueDisplayed: 0.1µF  [0402L]  (hidden comment: GRM155R71A104KA01D)
C331  ValueDisplayed: 100pF  [0603L]  (hidden comment: GRM1885C1H101JA01D)
C332  ValueDisplayed: 1µF  [0603L]  (hidden comment: GRM188R71C105KA12D)
C333  ValueDisplayed: 1µF  [0603L]  (hidden comment: GRM188R71C105KA12D)
C334  ValueDisplayed: 10µF  [1206_180]  (hidden comment: GRM31CR71C106KAC7L)
C335  ValueDisplayed: 1µF  Value2: 100V  [1210_220]  (hidden comment: C3225X7R2A105K200AA)
C336  ValueDisplayed: 0.01µF  Value2: 50V  [0603L]  (hidden comment: C0603C103K5RACTU)
C337  ValueDisplayed: 100pF  [0603L]  (hidden comment: GRM1885C1H101JA01D)
C338  ValueDisplayed: 0.033µF  [0603L]  (hidden comment: GRM188R71E333KA01D)
C339  ValueDisplayed: 0.033µF  [0603L]  (hidden comment: GRM188R71E333KA01D)
C340  ValueDisplayed: 1µF  Value2: 100V  [1210_220]  (hidden comment: C3225X7R2A105K200AA)
C341  ValueDisplayed: 0.01µF  Value2: 50V  [0603L]  (hidden comment: C0603C103K5RACTU)
C342  ValueDisplayed: 0.1µF  [0603L]  (hidden comment: C0603C104K5RACTU)
C343  ValueDisplayed: 0.047µF  [0603L]  (hidden comment: GRM188R71H473KA61D)
FRT+  Front Right Tweeter+  [TEC-SpadeLug_63066-1]
FRT-  Front Right Tweeter-  [TEC-SpadeLug_63066-1]
FRW+  Front Right Woofer+  [TEC-SpadeLug_63066-1]
FRW-  Front Right Woofer-  [TEC-SpadeLug_63066-1]
JP300  PBC03SAAN  [PBC03SAAN]  (value not drawn)
JP301  PBC03SAAN  [PBC03SAAN]  (value not drawn)
JP302  PBC03SAAN  [PBC03SAAN]  (value not drawn)
JP303  PBC03SAAN  [PBC03SAAN]  (value not drawn)
L300  ValueDisplayed: 10µH  [0603L]  (hidden comment: GLFR1608T100M-LR)
L301  ValueDisplayed: 10µH  [Coilcraft_RA7231-ALB]  (hidden comment: UA8014-ALD)
L302  ValueDisplayed: 10µH  [Coilcraft_RA7231-ALB]  (hidden comment: UA8014-ALD)
R300  ValueDisplayed: 10  [0603L]  (hidden comment: CRCW060310R0JNEA)
R301  ValueDisplayed: 499  [0603L]  (hidden comment: CRCW0603499RFKEA)
R302  ValueDisplayed: 100  [0603L]  (hidden comment: CRCW0603100RFKEA)
R303  ValueDisplayed: 499  [0603L]  (hidden comment: CRCW0603499RFKEA)
R304  ValueDisplayed: 3.3  [0603L]  (hidden comment: CRCW06033R30JNEA)
R305  ValueDisplayed: 499  [0603L]  (hidden comment: CRCW0603499RFKEA)
R306  ValueDisplayed: 100  [0603L]  (hidden comment: CRCW0603100RFKEA)
R307  ValueDisplayed: 499  [0603L]  (hidden comment: CRCW0603499RFKEA)
R308  ValueDisplayed: 100  [0603L]  (hidden comment: CRCW0603100RFKEA)
R309  ValueDisplayed: 3.3  [0603L]  (hidden comment: CRCW06033R30JNEA)
R310  DNP  ValueDisplayed: 10.0k  [0402L]
R311  DNP  ValueDisplayed: 10.0k  [0402L]
R312  ValueDisplayed: 10.0k  [0402L]  (hidden comment: ERJ-2RKF1002X)
R313  ValueDisplayed: 10.0k  [0402L]  (hidden comment: ERJ-2RKF1002X)
R314  ValueDisplayed: 10.0k  [0402L]  (hidden comment: ERJ-2RKF1002X)
R315  ValueDisplayed: 4.99k  [0402L]  (hidden comment: CRCW04024K99FKED)
R316  ValueDisplayed: 100  [0603L]  (hidden comment: CRCW0603100RFKEA)
R317  ValueDisplayed: 4.99k  [0402L]  (hidden comment: CRCW04024K99FKED)
R318  ValueDisplayed: 3.3  [0603L]  (hidden comment: CRCW06033R30JNEA)
R319  ValueDisplayed: 22.0k  [0603L]  (hidden comment: RC0603FR-0722KL)
R320  ValueDisplayed: 3.3  [0603L]  (hidden comment: CRCW06033R30JNEA)
U300  PCM5252RHBR  [RHB0032E]
U301  TPA3244DDWR  [DDW0044D_N]

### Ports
BCK3 (in), DIN0 (in), INA3 (in), INB3 (in), INC3 (in), IND3 (in), LRCK3 (in), OSC-IOM (in), OSC-IOP (in), SCK3 (in), SCL3 (in), SDA3 (bidir), ~{AMP-RESET3} (in), ~{CLIP_OTW3} (out), ~{FAULT3} (out)

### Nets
3.3V-4: C306.1 C307.1 C308.1 C309.1 R300.1 R310.2 R311.2 R312.1 R317.2 U300.4(DVDD) U300.5(CPVDD)
12V: C301.1 C324.1 L300.1 U301.1(GVDD_CD) U301.22(GVDD_AB)
GND: C300.2(-) C301.2 C302.1 C303.1 C304.2 C305.2 C306.2 C307.2 C308.2 C309.2 C311.2(-) C312.2 C313.1 C314.1 C315.2 C318.2 C324.2 C325.2 C326.2 C328.2 C330.2 C331.2 C332.1 C333.1 C335.2 C337.2 C340.2 C342.1 C343.2 R304.1 R309.1 R313.1 R314.1 R315.2 R318.1 R319.1 R320.1 U300.3(DGND) U300.7(CPGND) U300.15(AGND) U300.33(GND) U301.10(GND) U301.11(GND) U301.19(M2) U301.20(M1) U301.25(GND) U301.26(GND) U301.33(GND) U301.34(GND) U301.41(GND) U301.42(GND) U301.45(PowerPAD)
PVDD: C300.1(+) C302.2 C303.2 C311.1(+) C313.2 C314.2 U301.29(PVDD_AB) U301.30(PVDD_AB) U301.31(PVDD_AB) U301.36(PVDD_CD) U301.37(PVDD_CD) U301.38(PVDD_CD)
~{AMP-RESET3}: U301.5(~{RESET}) ; port ~{AMP-RESET3}
~{CLIP_OTW3}: U301.2(~{CLIP_OTW}) ; port ~{CLIP_OTW3}
~{FAULT3}: U301.4(~{FAULT}) ; port ~{FAULT3}
BCK3: U300.27(BCK) ; port BCK3
DAC3L+: C317.1 JP300.1 R301.2
DAC3L-: C317.2 JP301.1 R303.2
DAC3R+: C321.2 JP302.1 R307.2
DAC3R-: C321.1 JP303.1 R305.2
DIN0: U300.28(DIN) ; port DIN0
DVDD3: C332.2 U301.12(DVDD) U301.15(FREQ_ADJ)
FrontRightTweeter+: C315.1 C316.1 FRT+.1 L301.2
FrontRightTweeter-: C326.1 C327.1 FRT-.1 L301.3
FrontRightWoofer+: C335.1 C336.1 FRW+.1 L302.2
FrontRightWoofer-: C340.1 C341.1 FRW-.1 L302.3
INA3: JP300.3 ; port INA3
INB3: JP301.3 ; port INB3
INC3: JP302.3 ; port INC3
IND3: JP303.3 ; port IND3
INPUTA3: C318.1 R302.2 U301.18(INPUT_A)
INPUTB3: C325.1 R306.2 U301.17(INPUT_B)
INPUTC3: C331.1 R308.2 U301.7(INPUT_C)
INPUTD3: C337.1 R316.2 U301.6(INPUT_D)
LRCK3: U300.31(LRCK) ; port LRCK3
OSC-IOM: U301.14(OSC_IOM) ; port OSC-IOM
OSC-IOP: U301.13(OSC_IOP) ; port OSC-IOP
OUT3A: C320.1 L301.1 U301.27(OUT_A) U301.28(OUT_A)
OUT3B: C323.1 L301.4 U301.32(OUT_B)
OUT3C: C338.1 L302.1 U301.35(OUT_C)
OUT3D: C339.1 L302.4 U301.39(OUT_D) U301.40(OUT_D)
OUTLN3: R303.1 U300.11(OUTLN)
OUTLP3: R301.1 U300.10(OUTLP)
OUTRN3: R305.1 U300.12(OUTRN)
OUTRP3: R307.1 U300.13(OUTRP)
SCK3: U300.26(SCK) ; port SCK3
SCL3: U300.18(MC/SCL/ATT1) ; port SCL3
SDA3: U300.17(MOSI/SDA/ATT2) ; port SDA3
VDD3: C312.1 L300.2 U301.21(VDD)
NetC304_1: C304.1 C305.1 R300.2 U300.14(AVDD)
NetC310_1: C310.1 JP300.2
NetC310_2: C310.2 R302.1
NetC316_2: C316.2 R304.2
NetC319_1: C319.1 JP301.2
NetC319_2: C319.2 R306.1
NetC320_2: C320.2 U301.23(BST_A)
NetC322_1: C322.1 U300.6(CAPP)
NetC322_2: C322.2 U300.8(CAPM)
NetC323_2: C323.2 U301.24(BST_B)
NetC327_2: C327.2 R309.2
NetC328_1: C328.1 U300.9(VNEG)
NetC329_1: C329.1 JP302.2
NetC329_2: C329.2 R308.1
NetC330_1: C330.1 U300.2(LDOO)
NetC333_2: C333.2 U301.9(AVDD)
NetC334_1: C334.1 JP303.2
NetC334_2: C334.2 R316.1
NetC336_2: C336.2 R318.2
NetC338_2: C338.2 U301.43(BST_C)
NetC339_2: C339.2 U301.44(BST_D)
NetC341_2: C341.2 R320.2
NetC342_2: C342.2 U301.3(VBG)
NetC343_1: C343.1 U301.8(C_START)
NetR310_1: R310.1 R313.2 U300.32(MISO(GPIO1)/ADR1/FMT)
NetR311_1: R311.1 R314.2 U300.22(GPIO2/ADR2/GPO)
NetR312_2: R312.2 U300.1(XSMT)
NetR315_1: R315.1 U300.23(MODE1)
NetR317_1: R317.1 U300.24(MS/MODE2)
NetR319_2: R319.2 U301.16(OC_ADJ)

Not connected (* = marked no-connect by the designer): U300 16(VCOM/DEMP) 19(GPIO5/ATT0) 20(GPIO4/MAST) 21(GPIO3/AGNS) 25(GPIO6/FLT) 29(NC) 30(NC)

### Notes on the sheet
- FRONT RIGHT CHANNEL
- DUAL FP 1812/1206
- I2S
- ADDRESS
- SELECT
- (near U300) I2C-ADD=0x98
- I2C
- FROM
- INPUT HEADER
- MSP430
- TO MONITORS
- SURROUND CHANNEL

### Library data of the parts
C300 C311 = EEV-FK1H102M: as C200 on sheet TIDA-01414_UpChannel
C301 C312 C324 = C0603C104K5RACTU: as C201 on sheet TIDA-01414_UpChannel
C302 C303 C313 C314 = GRM31MR71H105KA88L: as C202 on sheet TIDA-01414_UpChannel
C304 C306 C308 = GRM188R61A106ME69D: as C204 on sheet TIDA-01414_UpChannel
C305 C307 C309 C330 = GRM155R71A104KA01D: as C205 on sheet TIDA-01414_UpChannel
C310 C319 C329 C334 = GRM31CR71C106KAC7L: as C210 on sheet TIDA-01414_UpChannel
C315 C326 C335 C340 = C3225X7R2A105K200AA: as C215 on sheet TIDA-01414_UpChannel
C316 C327 C336 C341 = C0603C103K5RACTU: as C216 on sheet TIDA-01414_UpChannel
C317 C321 = GRM1555C1H102JA01D: as C217 on sheet TIDA-01414_UpChannel
C318 C325 C331 C337 = GRM1885C1H101JA01D: as C218 on sheet TIDA-01414_UpChannel
C320 C323 C338 C339 = GRM188R71E333KA01D: as C220 on sheet TIDA-01414_UpChannel
C322 C328 = C1005X5R1A225K050BC: as C222 on sheet TIDA-01414_UpChannel
C332 C333 = GRM188R71C105KA12D: as C232 on sheet TIDA-01414_UpChannel
C342 = C0603C104K5RACTU: as C242 on sheet TIDA-01414_UpChannel
C343 = GRM188R71H473KA61D: as C243 on sheet TIDA-01414_UpChannel
FRT+ FRT- FRW+ FRW- = 63066-1: as UPL+ on sheet TIDA-01414_UpChannel
JP300-JP303 = SIP3-90_PBC03SAAN: as JP200-JP203 on sheet TIDA-01414_UpChannel
L300 = GLFR1608T100M-LR: as L200 on sheet TIDA-01414_UpChannel
L301 L302 = UA8014-ALD: as L201 on sheet TIDA-01414_UpChannel
R300 = CRCW060310R0JNEA: as R200 on sheet TIDA-01414_UpChannel
R301 R303 R305 R307 = CRCW0603499RFKEA: as R201 on sheet TIDA-01414_UpChannel
R302 R306 R308 R316 = CRCW0603100RFKEA: as R202 on sheet TIDA-01414_UpChannel
R304 R309 R318 R320 = CRCW06033R30JNEA: as R204 on sheet TIDA-01414_UpChannel
R310-R314 = ERJ-2RKF1002X: as R210-R214 on sheet TIDA-01414_UpChannel
R315 R317 = CRCW04024K99FKED: as R215 on sheet TIDA-01414_UpChannel
R319 = RC0603FR-0722KL: as R219 on sheet TIDA-01414_UpChannel
U300 = PCM5252RHBR: as U200 on sheet TIDA-01414_UpChannel
U301 = TPA3244DDWR: as U201 on sheet TIDA-01414_UpChannel

## Sheet TIDA-01414_FrontLeftChannel.SchDoc: Main Schematic
size 538 x 342 mm; Date: Not shown in title block; ApprovedBy: Not shown in title block; CheckedBy: Not shown in title block; Author: Not shown in title block; CompanyName: Not shown in title block; DrawnBy: LDN; Engineer: Not shown in title block; Organization: Not shown in title block; Address1: Not shown in title block; Address2: Not shown in title block; Address3: Not shown in title block; Address4: Not shown in title block; DocumentNumber: 6; Revision: Use project parameter SCH_Rev; SheetNumber: 6; SheetTotal: 12; PageSetup: Record=PageOptions¦CenterHorizontal=True¦CenterVertical=True¦PrintScale=1.00¦XCorrection=1.00¦YCorrection=1.00¦PrintKind=0¦BorderSize=5000000¦LeftOffset=0¦BottomOffset=0¦Orientation=2¦PaperLength=1000¦PaperWidth=1000¦Scale=100¦PaperSource=15¦PrintQuality=600¦MediaType=1¦DitherType=10¦PaperKind=Letter¦PrintScaleMode=1
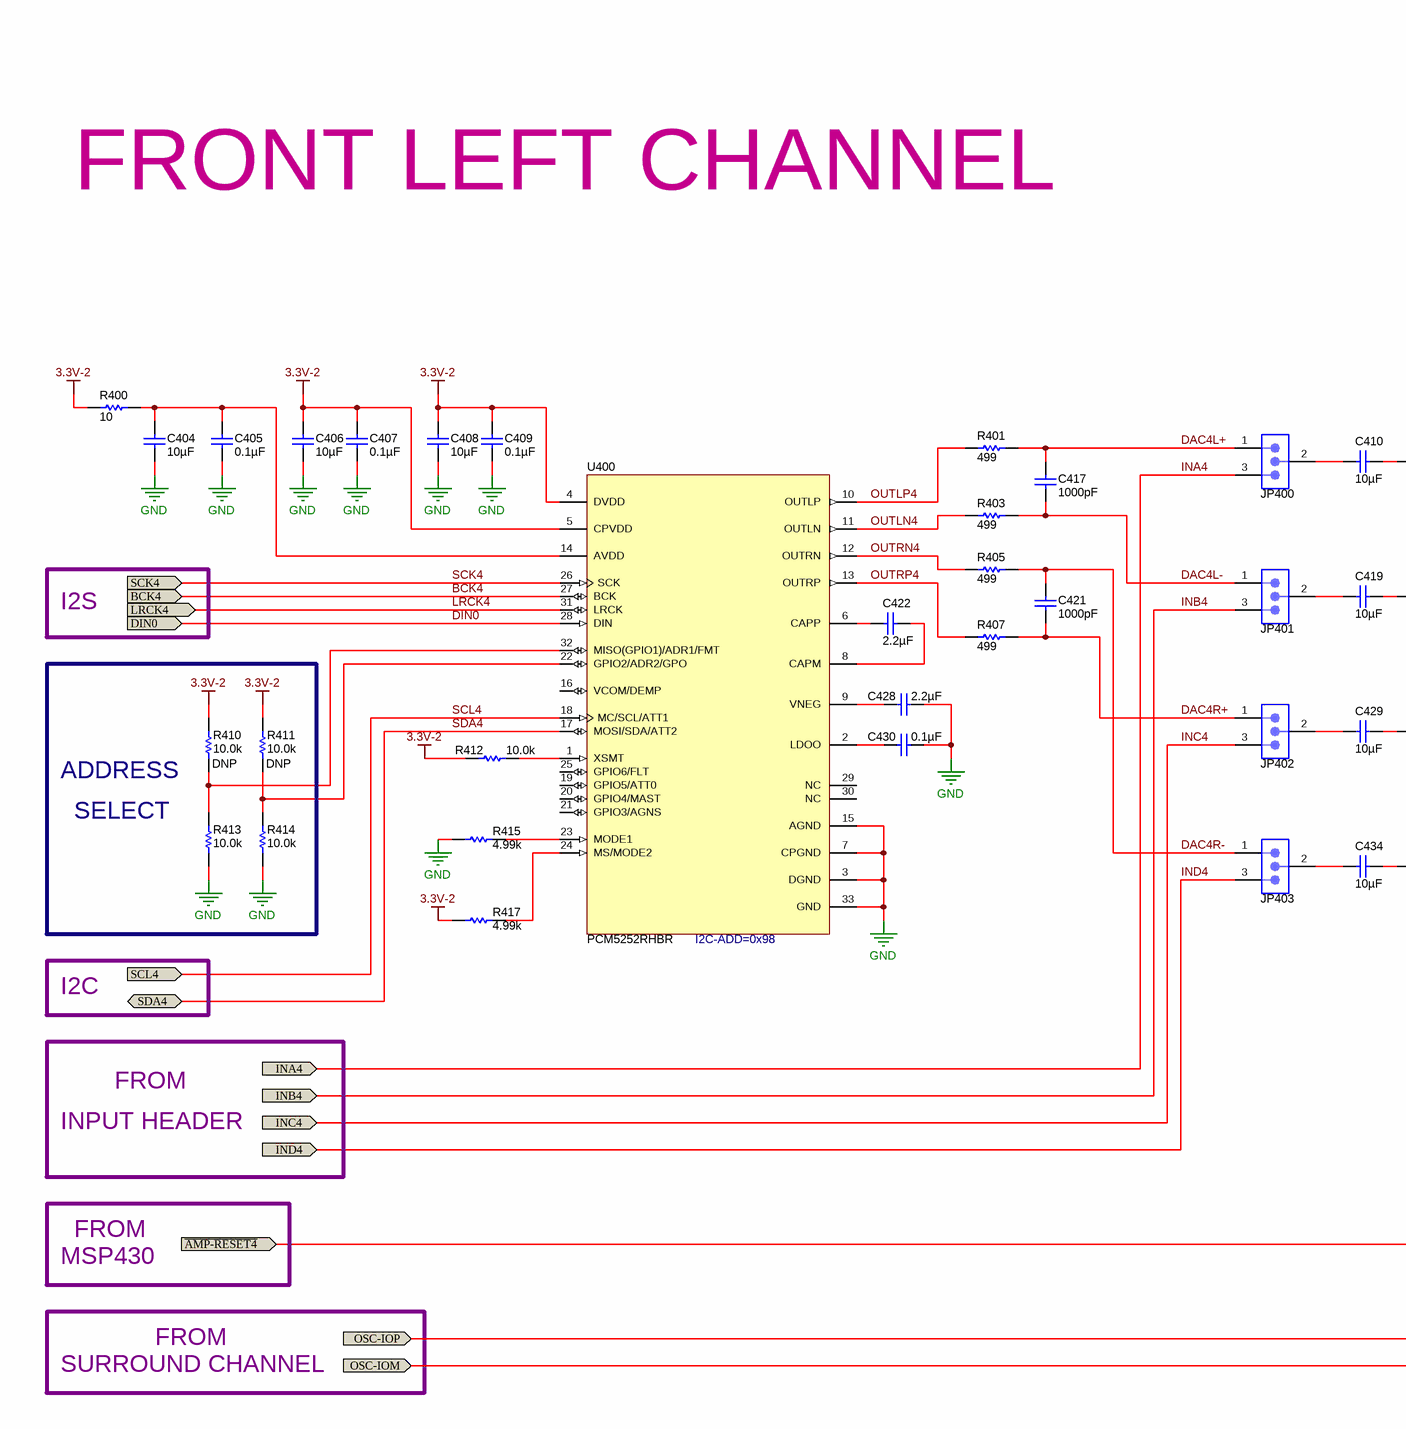
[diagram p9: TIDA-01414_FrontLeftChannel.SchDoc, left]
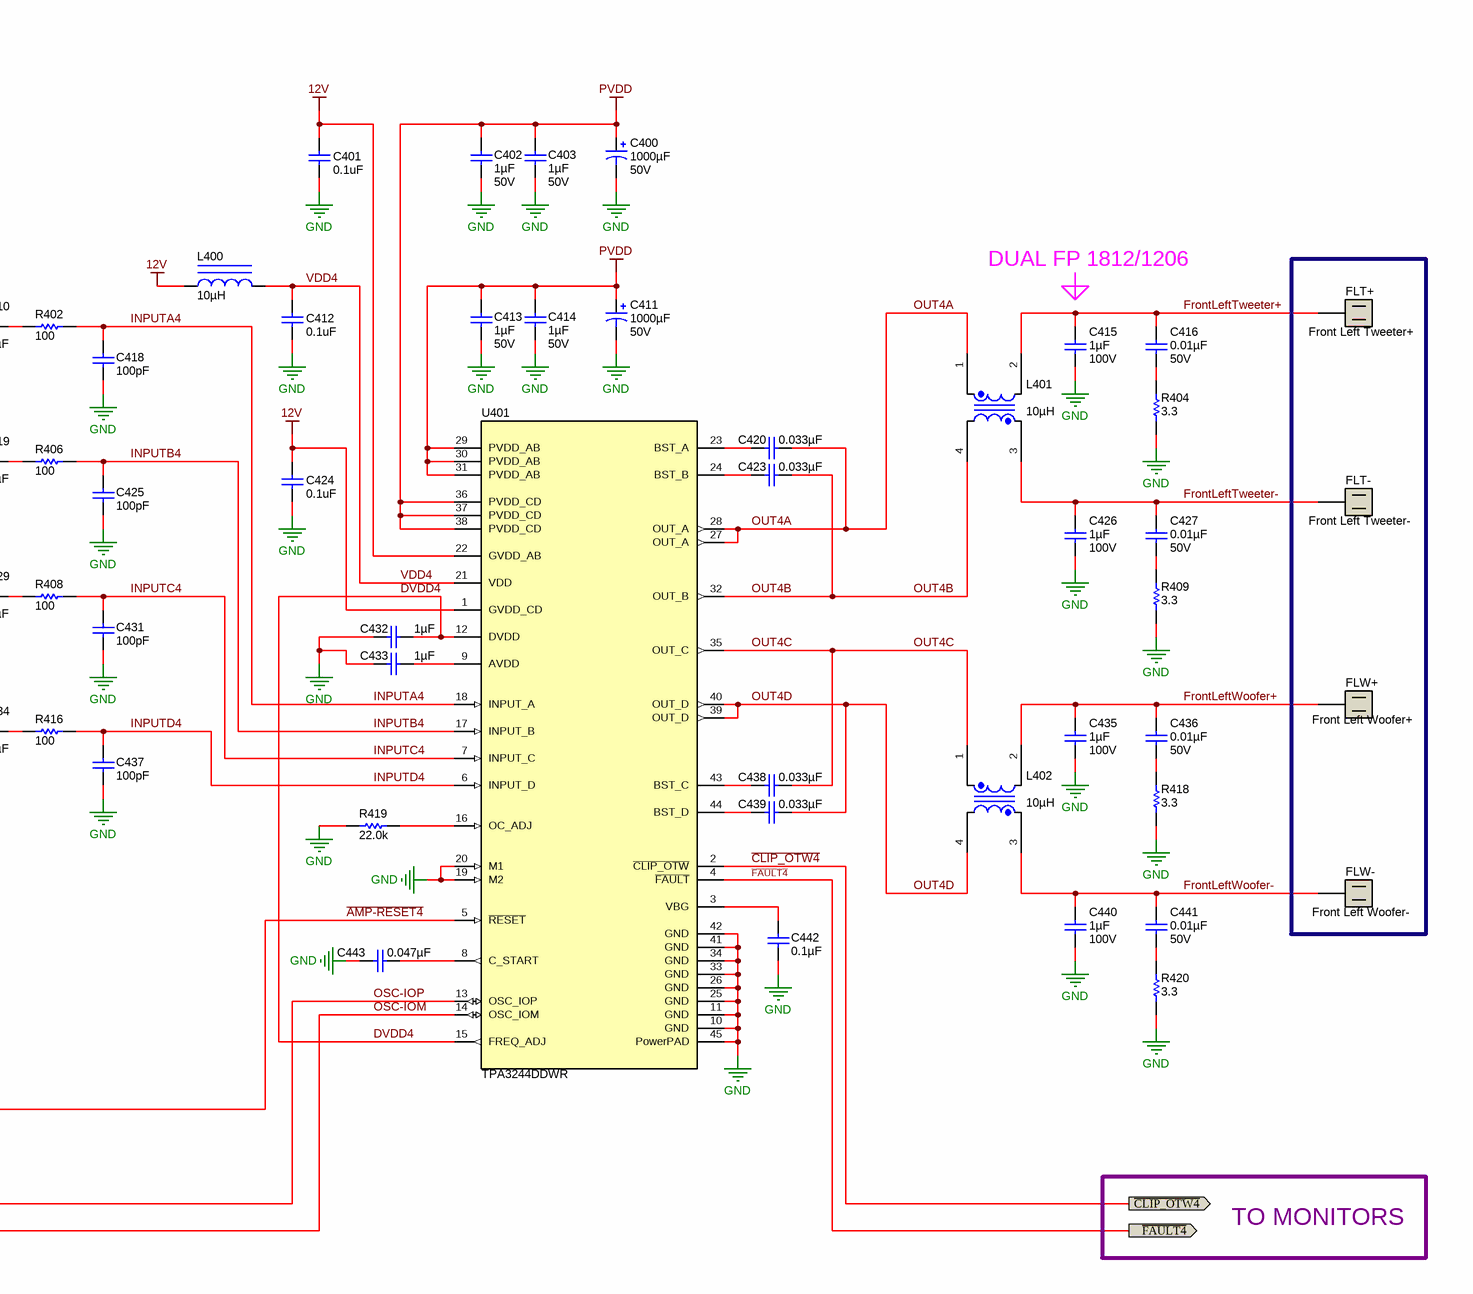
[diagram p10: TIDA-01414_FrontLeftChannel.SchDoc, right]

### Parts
C400  ValueDisplayed: 1000µF  Value2: 50V  [SM_RADIAL_J16]  (hidden comment: +)
C401  value 0.1uF  [0603L]  (hidden comment: C0603C104K5RACTU)
C402  ValueDisplayed: 1µF  Value2: 50V  [1206L]  (hidden comment: GRM31MR71H105KA88L)
C403  ValueDisplayed: 1µF  Value2: 50V  [1206L]  (hidden comment: GRM31MR71H105KA88L)
C404  ValueDisplayed: 10µF  [0603L]  (hidden comment: GRM188R61A106ME69D)
C405  ValueDisplayed: 0.1µF  [0402L]  (hidden comment: GRM155R71A104KA01D)
C406  ValueDisplayed: 10µF  [0603L]  (hidden comment: GRM188R61A106ME69D)
C407  ValueDisplayed: 0.1µF  [0402L]  (hidden comment: GRM155R71A104KA01D)
C408  ValueDisplayed: 10µF  [0603L]  (hidden comment: GRM188R61A106ME69D)
C409  ValueDisplayed: 0.1µF  [0402L]  (hidden comment: GRM155R71A104KA01D)
C410  ValueDisplayed: 10µF  [1206_180]  (hidden comment: GRM31CR71C106KAC7L)
C411  ValueDisplayed: 1000µF  Value2: 50V  [SM_RADIAL_J16]  (hidden comment: +)
C412  value 0.1uF  [0603L]  (hidden comment: C0603C104K5RACTU)
C413  ValueDisplayed: 1µF  Value2: 50V  [1206L]  (hidden comment: GRM31MR71H105KA88L)
C414  ValueDisplayed: 1µF  Value2: 50V  [1206L]  (hidden comment: GRM31MR71H105KA88L)
C415  ValueDisplayed: 1µF  Value2: 100V  [1210_220]  (hidden comment: C3225X7R2A105K200AA)
C416  ValueDisplayed: 0.01µF  Value2: 50V  [0603L]  (hidden comment: C0603C103K5RACTU)
C417  ValueDisplayed: 1000pF  [0402L]  (hidden comment: GRM1555C1H102JA01D)
C418  ValueDisplayed: 100pF  [0603L]  (hidden comment: GRM1885C1H101JA01D)
C419  ValueDisplayed: 10µF  [1206_180]  (hidden comment: GRM31CR71C106KAC7L)
C420  ValueDisplayed: 0.033µF  [0603L]  (hidden comment: GRM188R71E333KA01D)
C421  ValueDisplayed: 1000pF  [0402L]  (hidden comment: GRM1555C1H102JA01D)
C422  ValueDisplayed: 2.2µF  [0402L]  (hidden comment: C1005X5R1A225K050BC)
C423  ValueDisplayed: 0.033µF  [0603L]  (hidden comment: GRM188R71E333KA01D)
C424  value 0.1uF  [0603L]  (hidden comment: C0603C104K5RACTU)
C425  ValueDisplayed: 100pF  [0603L]  (hidden comment: GRM1885C1H101JA01D)
C426  ValueDisplayed: 1µF  Value2: 100V  [1210_220]  (hidden comment: C3225X7R2A105K200AA)
C427  ValueDisplayed: 0.01µF  Value2: 50V  [0603L]  (hidden comment: C0603C103K5RACTU)
C428  ValueDisplayed: 2.2µF  [0402L]  (hidden comment: C1005X5R1A225K050BC)
C429  ValueDisplayed: 10µF  [1206_180]  (hidden comment: GRM31CR71C106KAC7L)
C430  ValueDisplayed: 0.1µF  [0402L]  (hidden comment: GRM155R71A104KA01D)
C431  ValueDisplayed: 100pF  [0603L]  (hidden comment: GRM1885C1H101JA01D)
C432  ValueDisplayed: 1µF  [0603L]  (hidden comment: GRM188R71C105KA12D)
C433  ValueDisplayed: 1µF  [0603L]  (hidden comment: GRM188R71C105KA12D)
C434  ValueDisplayed: 10µF  [1206_180]  (hidden comment: GRM31CR71C106KAC7L)
C435  ValueDisplayed: 1µF  Value2: 100V  [1210_220]  (hidden comment: C3225X7R2A105K200AA)
C436  ValueDisplayed: 0.01µF  Value2: 50V  [0603L]  (hidden comment: C0603C103K5RACTU)
C437  ValueDisplayed: 100pF  [0603L]  (hidden comment: GRM1885C1H101JA01D)
C438  ValueDisplayed: 0.033µF  [0603L]  (hidden comment: GRM188R71E333KA01D)
C439  ValueDisplayed: 0.033µF  [0603L]  (hidden comment: GRM188R71E333KA01D)
C440  ValueDisplayed: 1µF  Value2: 100V  [1210_220]  (hidden comment: C3225X7R2A105K200AA)
C441  ValueDisplayed: 0.01µF  Value2: 50V  [0603L]  (hidden comment: C0603C103K5RACTU)
C442  ValueDisplayed: 0.1µF  [0603L]  (hidden comment: C0603C104K5RACTU)
C443  ValueDisplayed: 0.047µF  [0603L]  (hidden comment: GRM188R71H473KA61D)
FLT+  Front Left Tweeter+  [TEC-SpadeLug_63066-1]
FLT-  Front Left Tweeter-  [TEC-SpadeLug_63066-1]
FLW+  Front Left Woofer+  [TEC-SpadeLug_63066-1]
FLW-  Front Left Woofer-  [TEC-SpadeLug_63066-1]
JP400  PBC03SAAN  [PBC03SAAN]  (value not drawn)
JP401  PBC03SAAN  [PBC03SAAN]  (value not drawn)
JP402  PBC03SAAN  [PBC03SAAN]  (value not drawn)
JP403  PBC03SAAN  [PBC03SAAN]  (value not drawn)
L400  ValueDisplayed: 10µH  [0603L]  (hidden comment: GLFR1608T100M-LR)
L401  ValueDisplayed: 10µH  [Coilcraft_RA7231-ALB]  (hidden comment: UA8014-ALD)
L402  ValueDisplayed: 10µH  [Coilcraft_RA7231-ALB]  (hidden comment: UA8014-ALD)
R400  ValueDisplayed: 10  [0603L]  (hidden comment: CRCW060310R0JNEA)
R401  ValueDisplayed: 499  [0603L]  (hidden comment: CRCW0603499RFKEA)
R402  ValueDisplayed: 100  [0603L]  (hidden comment: CRCW0603100RFKEA)
R403  ValueDisplayed: 499  [0603L]  (hidden comment: CRCW0603499RFKEA)
R404  ValueDisplayed: 3.3  [0603L]  (hidden comment: CRCW06033R30JNEA)
R405  ValueDisplayed: 499  [0603L]  (hidden comment: CRCW0603499RFKEA)
R406  ValueDisplayed: 100  [0603L]  (hidden comment: CRCW0603100RFKEA)
R407  ValueDisplayed: 499  [0603L]  (hidden comment: CRCW0603499RFKEA)
R408  ValueDisplayed: 100  [0603L]  (hidden comment: CRCW0603100RFKEA)
R409  ValueDisplayed: 3.3  [0603L]  (hidden comment: CRCW06033R30JNEA)
R410  DNP  ValueDisplayed: 10.0k  [0402L]
R411  DNP  ValueDisplayed: 10.0k  [0402L]
R412  ValueDisplayed: 10.0k  [0402L]  (hidden comment: ERJ-2RKF1002X)
R413  ValueDisplayed: 10.0k  [0402L]  (hidden comment: ERJ-2RKF1002X)
R414  ValueDisplayed: 10.0k  [0402L]  (hidden comment: ERJ-2RKF1002X)
R415  ValueDisplayed: 4.99k  [0402L]  (hidden comment: CRCW04024K99FKED)
R416  ValueDisplayed: 100  [0603L]  (hidden comment: CRCW0603100RFKEA)
R417  ValueDisplayed: 4.99k  [0402L]  (hidden comment: CRCW04024K99FKED)
R418  ValueDisplayed: 3.3  [0603L]  (hidden comment: CRCW06033R30JNEA)
R419  ValueDisplayed: 22.0k  [0603L]  (hidden comment: RC0603FR-0722KL)
R420  ValueDisplayed: 3.3  [0603L]  (hidden comment: CRCW06033R30JNEA)
U400  PCM5252RHBR  [RHB0032E]
U401  TPA3244DDWR  [DDW0044D_N]

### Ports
BCK4 (in), DIN0 (in), INA4 (in), INB4 (in), INC4 (in), IND4 (in), LRCK4 (in), OSC-IOM (in), OSC-IOP (in), SCK4 (in), SCL4 (in), SDA4 (bidir), ~{AMP-RESET4} (in), ~{CLIP_OTW4} (out), ~{FAULT4} (out)

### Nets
3.3V-2: C406.1 C407.1 C408.1 C409.1 R400.1 R410.2 R411.2 R412.1 R417.2 U400.4(DVDD) U400.5(CPVDD)
12V: C401.1 C424.1 L400.1 U401.1(GVDD_CD) U401.22(GVDD_AB)
GND: C400.2(-) C401.2 C402.1 C403.1 C404.2 C405.2 C406.2 C407.2 C408.2 C409.2 C411.2(-) C412.2 C413.1 C414.1 C415.2 C418.2 C424.2 C425.2 C426.2 C428.2 C430.2 C431.2 C432.1 C433.1 C435.2 C437.2 C440.2 C442.1 C443.2 R404.1 R409.1 R413.1 R414.1 R415.2 R418.1 R419.1 R420.1 U400.3(DGND) U400.7(CPGND) U400.15(AGND) U400.33(GND) U401.10(GND) U401.11(GND) U401.19(M2) U401.20(M1) U401.25(GND) U401.26(GND) U401.33(GND) U401.34(GND) U401.41(GND) U401.42(GND) U401.45(PowerPAD)
PVDD: C400.1(+) C402.2 C403.2 C411.1(+) C413.2 C414.2 U401.29(PVDD_AB) U401.30(PVDD_AB) U401.31(PVDD_AB) U401.36(PVDD_CD) U401.37(PVDD_CD) U401.38(PVDD_CD)
~{AMP-RESET4}: U401.5(~{RESET}) ; port ~{AMP-RESET4}
~{CLIP_OTW4}: U401.2(~{CLIP_OTW}) ; port ~{CLIP_OTW4}
~{FAULT4}: U401.4(~{FAULT}) ; port ~{FAULT4}
BCK4: U400.27(BCK) ; port BCK4
DAC4L+: C417.1 JP400.1 R401.2
DAC4L-: C417.2 JP401.1 R403.2
DAC4R+: C421.2 JP402.1 R407.2
DAC4R-: C421.1 JP403.1 R405.2
DIN0: U400.28(DIN) ; port DIN0
DVDD4: C432.2 U401.12(DVDD) U401.15(FREQ_ADJ)
FrontLeftTweeter+: C415.1 C416.1 FLT+.1 L401.2
FrontLeftTweeter-: C426.1 C427.1 FLT-.1 L401.3
FrontLeftWoofer+: C435.1 C436.1 FLW+.1 L402.2
FrontLeftWoofer-: C440.1 C441.1 FLW-.1 L402.3
INA4: JP400.3 ; port INA4
INB4: JP401.3 ; port INB4
INC4: JP402.3 ; port INC4
IND4: JP403.3 ; port IND4
INPUTA4: C418.1 R402.2 U401.18(INPUT_A)
INPUTB4: C425.1 R406.2 U401.17(INPUT_B)
INPUTC4: C431.1 R408.2 U401.7(INPUT_C)
INPUTD4: C437.1 R416.2 U401.6(INPUT_D)
LRCK4: U400.31(LRCK) ; port LRCK4
OSC-IOM: U401.14(OSC_IOM) ; port OSC-IOM
OSC-IOP: U401.13(OSC_IOP) ; port OSC-IOP
OUT4A: C420.1 L401.1 U401.27(OUT_A) U401.28(OUT_A)
OUT4B: C423.1 L401.4 U401.32(OUT_B)
OUT4C: C438.1 L402.1 U401.35(OUT_C)
OUT4D: C439.1 L402.4 U401.39(OUT_D) U401.40(OUT_D)
OUTLN4: R403.1 U400.11(OUTLN)
OUTLP4: R401.1 U400.10(OUTLP)
OUTRN4: R405.1 U400.12(OUTRN)
OUTRP4: R407.1 U400.13(OUTRP)
SCK4: U400.26(SCK) ; port SCK4
SCL4: U400.18(MC/SCL/ATT1) ; port SCL4
SDA4: U400.17(MOSI/SDA/ATT2) ; port SDA4
VDD4: C412.1 L400.2 U401.21(VDD)
NetC404_1: C404.1 C405.1 R400.2 U400.14(AVDD)
NetC410_1: C410.1 JP400.2
NetC410_2: C410.2 R402.1
NetC416_2: C416.2 R404.2
NetC419_1: C419.1 JP401.2
NetC419_2: C419.2 R406.1
NetC420_2: C420.2 U401.23(BST_A)
NetC422_1: C422.1 U400.6(CAPP)
NetC422_2: C422.2 U400.8(CAPM)
NetC423_2: C423.2 U401.24(BST_B)
NetC427_2: C427.2 R409.2
NetC428_1: C428.1 U400.9(VNEG)
NetC429_1: C429.1 JP402.2
NetC429_2: C429.2 R408.1
NetC430_1: C430.1 U400.2(LDOO)
NetC433_2: C433.2 U401.9(AVDD)
NetC434_1: C434.1 JP403.2
NetC434_2: C434.2 R416.1
NetC436_2: C436.2 R418.2
NetC438_2: C438.2 U401.43(BST_C)
NetC439_2: C439.2 U401.44(BST_D)
NetC441_2: C441.2 R420.2
NetC442_2: C442.2 U401.3(VBG)
NetC443_1: C443.1 U401.8(C_START)
NetR410_1: R410.1 R413.2 U400.32(MISO(GPIO1)/ADR1/FMT)
NetR411_1: R411.1 R414.2 U400.22(GPIO2/ADR2/GPO)
NetR412_2: R412.2 U400.1(XSMT)
NetR415_1: R415.1 U400.23(MODE1)
NetR417_1: R417.1 U400.24(MS/MODE2)
NetR419_2: R419.2 U401.16(OC_ADJ)

Not connected (* = marked no-connect by the designer): U400 16(VCOM/DEMP) 19(GPIO5/ATT0) 20(GPIO4/MAST) 21(GPIO3/AGNS) 25(GPIO6/FLT) 29(NC) 30(NC)

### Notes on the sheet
- FRONT LEFT CHANNEL
- DUAL FP 1812/1206
- I2S
- ADDRESS
- SELECT
- (near U400) I2C-ADD=0x98
- I2C
- FROM
- INPUT HEADER
- MSP430
- TO MONITORS
- SURROUND CHANNEL

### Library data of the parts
C400 C411 = EEV-FK1H102M: as C200 on sheet TIDA-01414_UpChannel
C401 C412 C424 = C0603C104K5RACTU: as C201 on sheet TIDA-01414_UpChannel
C402 C403 C413 C414 = GRM31MR71H105KA88L: as C202 on sheet TIDA-01414_UpChannel
C404 C406 C408 = GRM188R61A106ME69D: as C204 on sheet TIDA-01414_UpChannel
C405 C407 C409 C430 = GRM155R71A104KA01D: as C205 on sheet TIDA-01414_UpChannel
C410 C419 C429 C434 = GRM31CR71C106KAC7L: as C210 on sheet TIDA-01414_UpChannel
C415 C426 C435 C440 = C3225X7R2A105K200AA: as C215 on sheet TIDA-01414_UpChannel
C416 C427 C436 C441 = C0603C103K5RACTU: as C216 on sheet TIDA-01414_UpChannel
C417 C421 = GRM1555C1H102JA01D: as C217 on sheet TIDA-01414_UpChannel
C418 C425 C431 C437 = GRM1885C1H101JA01D: as C218 on sheet TIDA-01414_UpChannel
C420 C423 C438 C439 = GRM188R71E333KA01D: as C220 on sheet TIDA-01414_UpChannel
C422 C428 = C1005X5R1A225K050BC: as C222 on sheet TIDA-01414_UpChannel
C432 C433 = GRM188R71C105KA12D: as C232 on sheet TIDA-01414_UpChannel
C442 = C0603C104K5RACTU: as C242 on sheet TIDA-01414_UpChannel
C443 = GRM188R71H473KA61D: as C243 on sheet TIDA-01414_UpChannel
FLT+ FLT- FLW+ FLW- = 63066-1: as UPL+ on sheet TIDA-01414_UpChannel
JP400-JP403 = SIP3-90_PBC03SAAN: as JP200-JP203 on sheet TIDA-01414_UpChannel
L400 = GLFR1608T100M-LR: as L200 on sheet TIDA-01414_UpChannel
L401 L402 = UA8014-ALD: as L201 on sheet TIDA-01414_UpChannel
R400 = CRCW060310R0JNEA: as R200 on sheet TIDA-01414_UpChannel
R401 R403 R405 R407 = CRCW0603499RFKEA: as R201 on sheet TIDA-01414_UpChannel
R402 R406 R408 R416 = CRCW0603100RFKEA: as R202 on sheet TIDA-01414_UpChannel
R404 R409 R418 R420 = CRCW06033R30JNEA: as R204 on sheet TIDA-01414_UpChannel
R410-R414 = ERJ-2RKF1002X: as R210-R214 on sheet TIDA-01414_UpChannel
R415 R417 = CRCW04024K99FKED: as R215 on sheet TIDA-01414_UpChannel
R419 = RC0603FR-0722KL: as R219 on sheet TIDA-01414_UpChannel
U400 = PCM5252RHBR: as U200 on sheet TIDA-01414_UpChannel
U401 = TPA3244DDWR: as U201 on sheet TIDA-01414_UpChannel

## Sheet TIDA-01414_CenterChannel.SchDoc: Main Schematic
size 538 x 342 mm; Date: Not shown in title block; ApprovedBy: Not shown in title block; CheckedBy: Not shown in title block; Author: Not shown in title block; CompanyName: Not shown in title block; DrawnBy: LDN; Engineer: Not shown in title block; Organization: Not shown in title block; Address1: Not shown in title block; Address2: Not shown in title block; Address3: Not shown in title block; Address4: Not shown in title block; DocumentNumber: 7; Revision: Use project parameter SCH_Rev; SheetNumber: 7; SheetTotal: 12; PageSetup: Record=PageOptions¦CenterHorizontal=True¦CenterVertical=True¦PrintScale=1.00¦XCorrection=1.00¦YCorrection=1.00¦PrintKind=0¦BorderSize=5000000¦LeftOffset=0¦BottomOffset=0¦Orientation=2¦PaperLength=1000¦PaperWidth=1000¦Scale=100¦PaperSource=15¦PrintQuality=600¦MediaType=1¦DitherType=10¦PaperKind=Letter¦PrintScaleMode=1
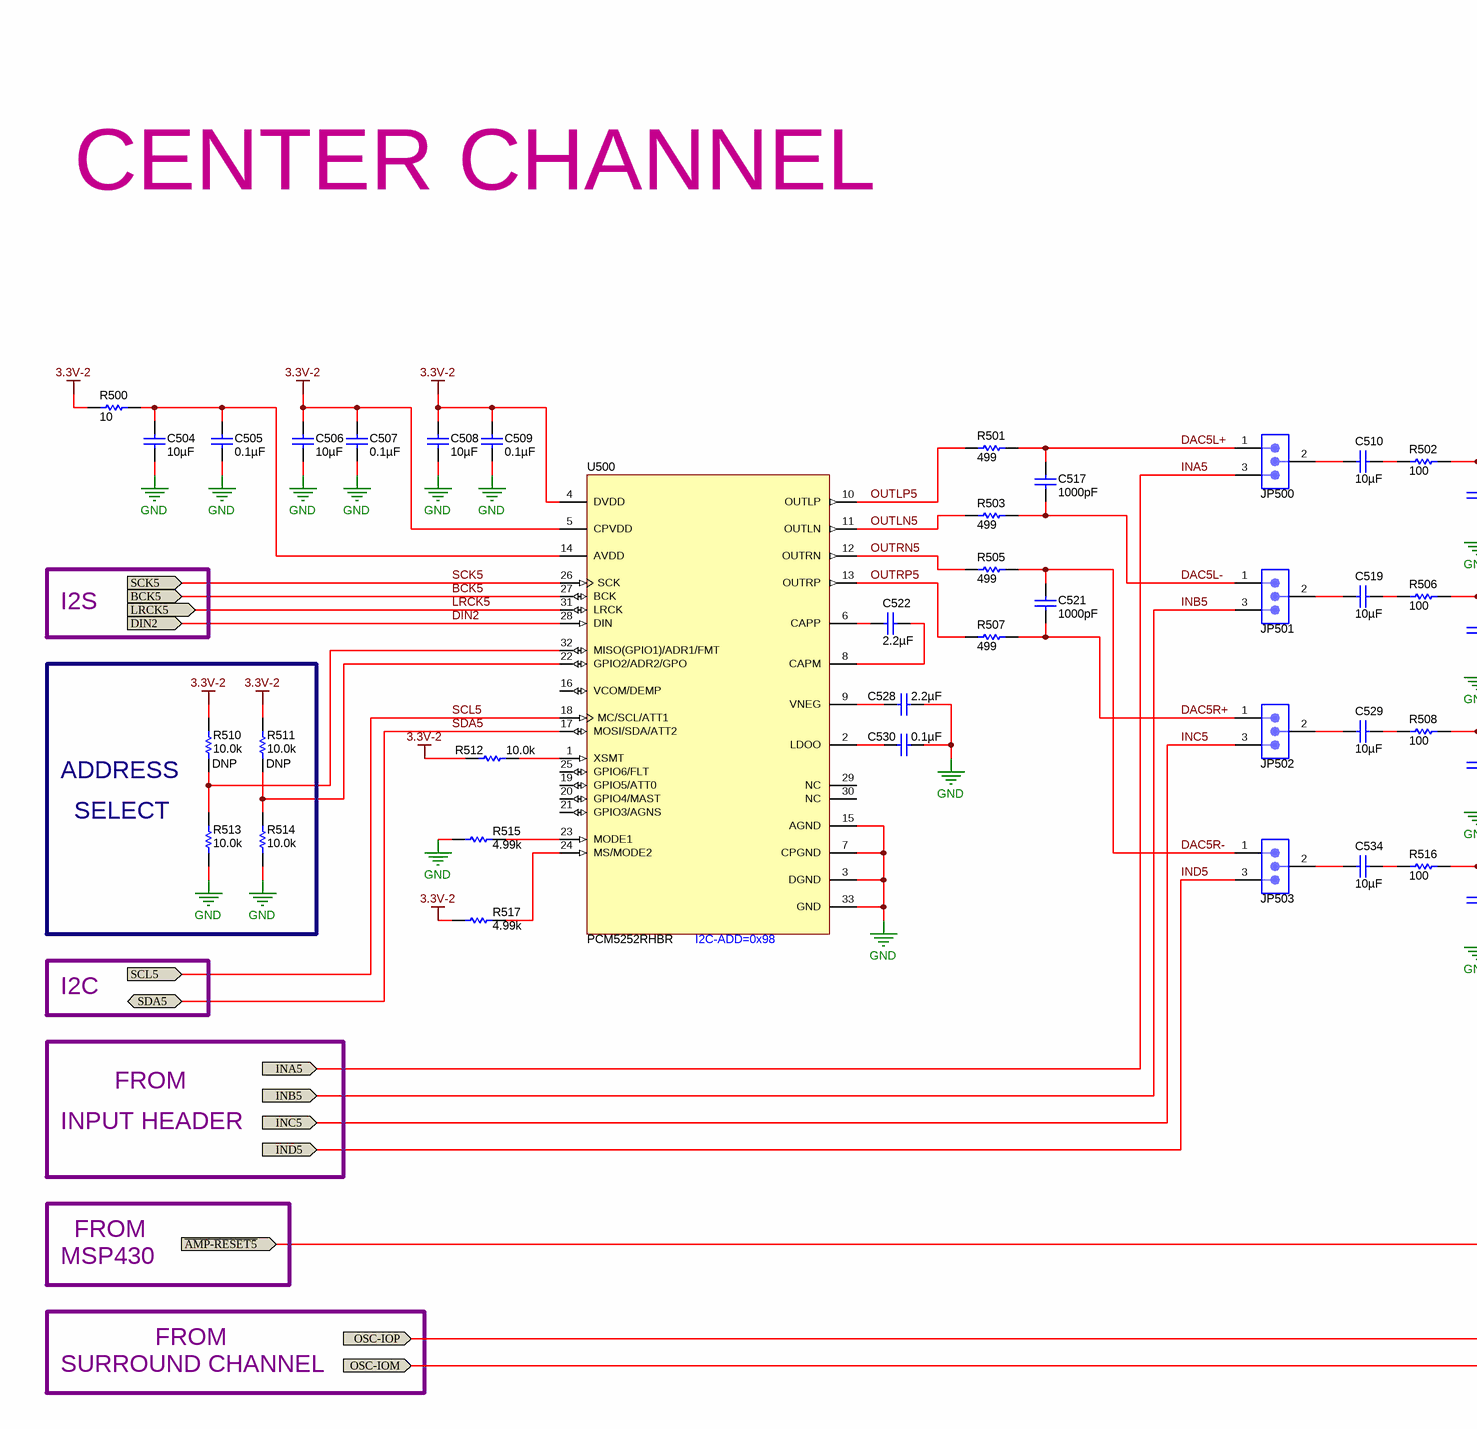
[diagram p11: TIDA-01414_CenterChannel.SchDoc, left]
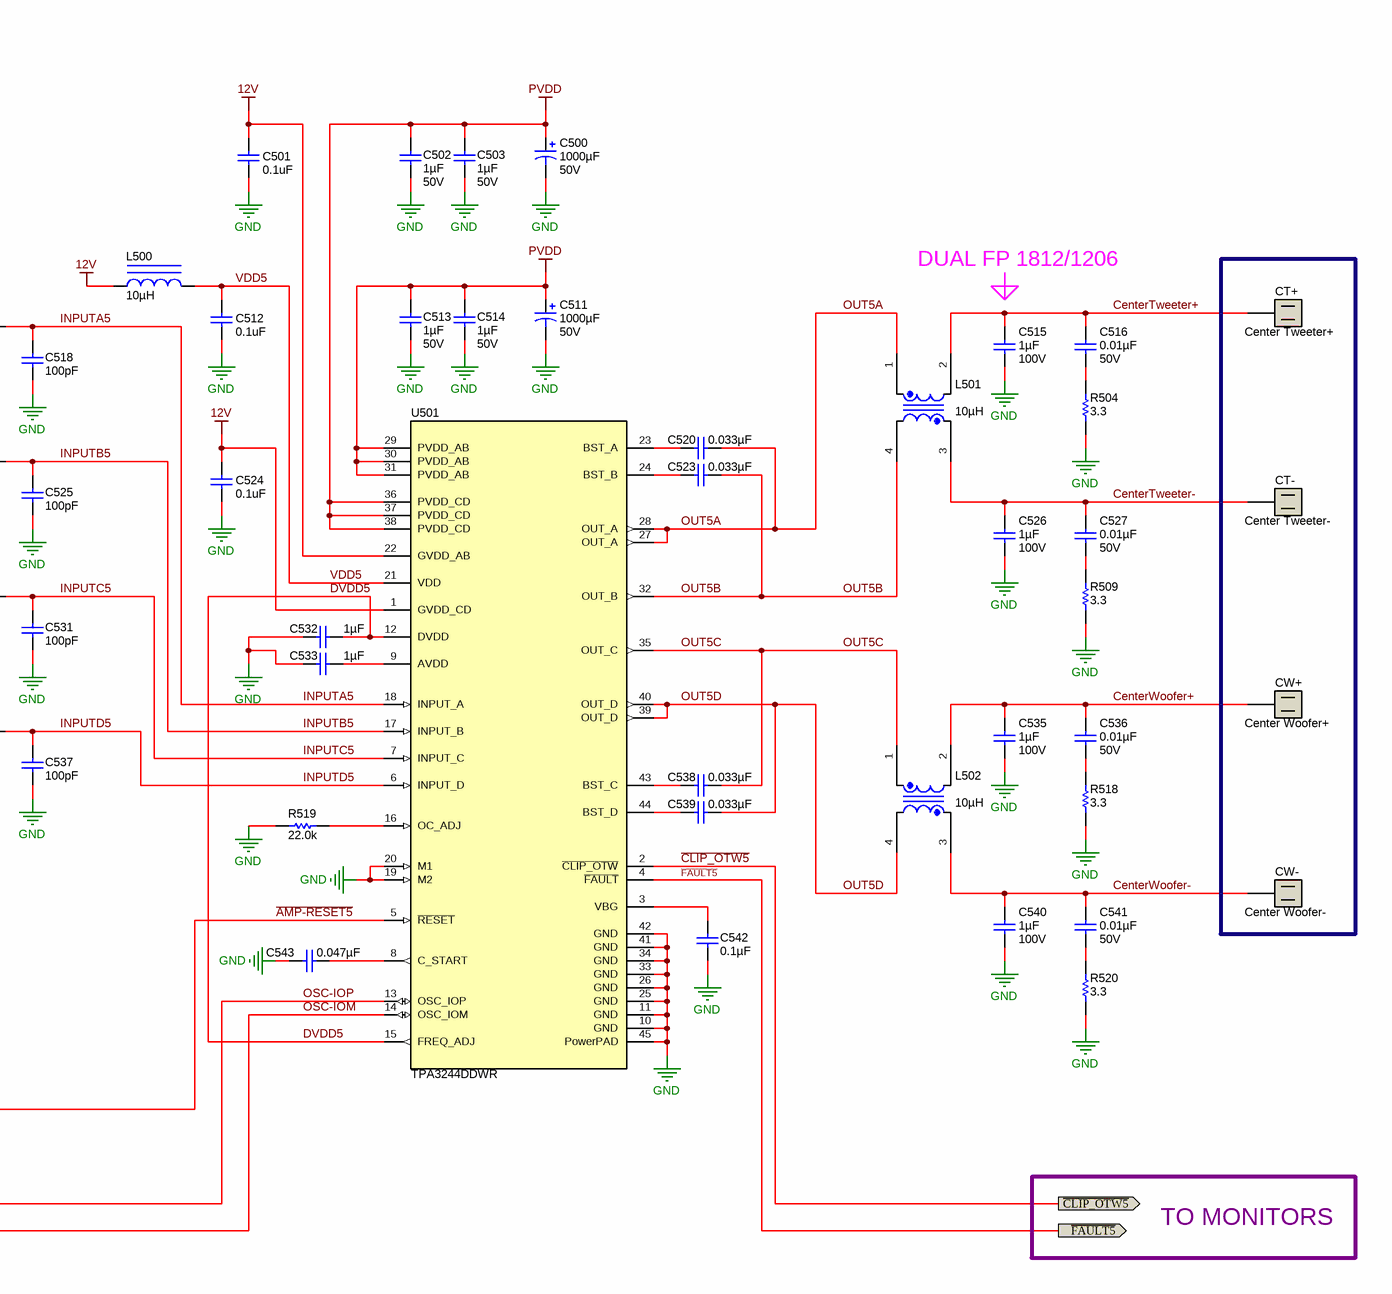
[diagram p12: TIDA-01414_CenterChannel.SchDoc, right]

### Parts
C500  ValueDisplayed: 1000µF  Value2: 50V  [SM_RADIAL_J16]  (hidden comment: +)
C501  value 0.1uF  [0603L]  (hidden comment: C0603C104K5RACTU)
C502  ValueDisplayed: 1µF  Value2: 50V  [1206L]  (hidden comment: GRM31MR71H105KA88L)
C503  ValueDisplayed: 1µF  Value2: 50V  [1206L]  (hidden comment: GRM31MR71H105KA88L)
C504  ValueDisplayed: 10µF  [0603L]  (hidden comment: GRM188R61A106ME69D)
C505  ValueDisplayed: 0.1µF  [0402L]  (hidden comment: GRM155R71A104KA01D)
C506  ValueDisplayed: 10µF  [0603L]  (hidden comment: GRM188R61A106ME69D)
C507  ValueDisplayed: 0.1µF  [0402L]  (hidden comment: GRM155R71A104KA01D)
C508  ValueDisplayed: 10µF  [0603L]  (hidden comment: GRM188R61A106ME69D)
C509  ValueDisplayed: 0.1µF  [0402L]  (hidden comment: GRM155R71A104KA01D)
C510  ValueDisplayed: 10µF  [1206_180]  (hidden comment: GRM31CR71C106KAC7L)
C511  ValueDisplayed: 1000µF  Value2: 50V  [SM_RADIAL_J16]  (hidden comment: +)
C512  value 0.1uF  [0603L]  (hidden comment: C0603C104K5RACTU)
C513  ValueDisplayed: 1µF  Value2: 50V  [1206L]  (hidden comment: GRM31MR71H105KA88L)
C514  ValueDisplayed: 1µF  Value2: 50V  [1206L]  (hidden comment: GRM31MR71H105KA88L)
C515  ValueDisplayed: 1µF  Value2: 100V  [1210_220]  (hidden comment: C3225X7R2A105K200AA)
C516  ValueDisplayed: 0.01µF  Value2: 50V  [0603L]  (hidden comment: C0603C103K5RACTU)
C517  ValueDisplayed: 1000pF  [0402L]  (hidden comment: GRM1555C1H102JA01D)
C518  ValueDisplayed: 100pF  [0603L]  (hidden comment: GRM1885C1H101JA01D)
C519  ValueDisplayed: 10µF  [1206_180]  (hidden comment: GRM31CR71C106KAC7L)
C520  ValueDisplayed: 0.033µF  [0603L]  (hidden comment: GRM188R71E333KA01D)
C521  ValueDisplayed: 1000pF  [0402L]  (hidden comment: GRM1555C1H102JA01D)
C522  ValueDisplayed: 2.2µF  [0402L]  (hidden comment: C1005X5R1A225K050BC)
C523  ValueDisplayed: 0.033µF  [0603L]  (hidden comment: GRM188R71E333KA01D)
C524  value 0.1uF  [0603L]  (hidden comment: C0603C104K5RACTU)
C525  ValueDisplayed: 100pF  [0603L]  (hidden comment: GRM1885C1H101JA01D)
C526  ValueDisplayed: 1µF  Value2: 100V  [1210_220]  (hidden comment: C3225X7R2A105K200AA)
C527  ValueDisplayed: 0.01µF  Value2: 50V  [0603L]  (hidden comment: C0603C103K5RACTU)
C528  ValueDisplayed: 2.2µF  [0402L]  (hidden comment: C1005X5R1A225K050BC)
C529  ValueDisplayed: 10µF  [1206_180]  (hidden comment: GRM31CR71C106KAC7L)
C530  ValueDisplayed: 0.1µF  [0402L]  (hidden comment: GRM155R71A104KA01D)
C531  ValueDisplayed: 100pF  [0603L]  (hidden comment: GRM1885C1H101JA01D)
C532  ValueDisplayed: 1µF  [0603L]  (hidden comment: GRM188R71C105KA12D)
C533  ValueDisplayed: 1µF  [0603L]  (hidden comment: GRM188R71C105KA12D)
C534  ValueDisplayed: 10µF  [1206_180]  (hidden comment: GRM31CR71C106KAC7L)
C535  ValueDisplayed: 1µF  Value2: 100V  [1210_220]  (hidden comment: C3225X7R2A105K200AA)
C536  ValueDisplayed: 0.01µF  Value2: 50V  [0603L]  (hidden comment: C0603C103K5RACTU)
C537  ValueDisplayed: 100pF  [0603L]  (hidden comment: GRM1885C1H101JA01D)
C538  ValueDisplayed: 0.033µF  [0603L]  (hidden comment: GRM188R71E333KA01D)
C539  ValueDisplayed: 0.033µF  [0603L]  (hidden comment: GRM188R71E333KA01D)
C540  ValueDisplayed: 1µF  Value2: 100V  [1210_220]  (hidden comment: C3225X7R2A105K200AA)
C541  ValueDisplayed: 0.01µF  Value2: 50V  [0603L]  (hidden comment: C0603C103K5RACTU)
C542  ValueDisplayed: 0.1µF  [0603L]  (hidden comment: C0603C104K5RACTU)
C543  ValueDisplayed: 0.047µF  [0603L]  (hidden comment: GRM188R71H473KA61D)
CT+  Center Tweeter+  [TEC-SpadeLug_63066-1]
CT-  Center Tweeter-  [TEC-SpadeLug_63066-1]
CW+  Center Woofer+  [TEC-SpadeLug_63066-1]
CW-  Center Woofer-  [TEC-SpadeLug_63066-1]
JP500  PBC03SAAN  [PBC03SAAN]  (value not drawn)
JP501  PBC03SAAN  [PBC03SAAN]  (value not drawn)
JP502  PBC03SAAN  [PBC03SAAN]  (value not drawn)
JP503  PBC03SAAN  [PBC03SAAN]  (value not drawn)
L500  ValueDisplayed: 10µH  [0603L]  (hidden comment: GLFR1608T100M-LR)
L501  ValueDisplayed: 10µH  [Coilcraft_RA7231-ALB]  (hidden comment: UA8014-ALD)
L502  ValueDisplayed: 10µH  [Coilcraft_RA7231-ALB]  (hidden comment: UA8014-ALD)
R500  ValueDisplayed: 10  [0603L]  (hidden comment: CRCW060310R0JNEA)
R501  ValueDisplayed: 499  [0603L]  (hidden comment: CRCW0603499RFKEA)
R502  ValueDisplayed: 100  [0603L]  (hidden comment: CRCW0603100RFKEA)
R503  ValueDisplayed: 499  [0603L]  (hidden comment: CRCW0603499RFKEA)
R504  ValueDisplayed: 3.3  [0603L]  (hidden comment: CRCW06033R30JNEA)
R505  ValueDisplayed: 499  [0603L]  (hidden comment: CRCW0603499RFKEA)
R506  ValueDisplayed: 100  [0603L]  (hidden comment: CRCW0603100RFKEA)
R507  ValueDisplayed: 499  [0603L]  (hidden comment: CRCW0603499RFKEA)
R508  ValueDisplayed: 100  [0603L]  (hidden comment: CRCW0603100RFKEA)
R509  ValueDisplayed: 3.3  [0603L]  (hidden comment: CRCW06033R30JNEA)
R510  DNP  ValueDisplayed: 10.0k  [0402L]
R511  DNP  ValueDisplayed: 10.0k  [0402L]
R512  ValueDisplayed: 10.0k  [0402L]  (hidden comment: ERJ-2RKF1002X)
R513  ValueDisplayed: 10.0k  [0402L]  (hidden comment: ERJ-2RKF1002X)
R514  ValueDisplayed: 10.0k  [0402L]  (hidden comment: ERJ-2RKF1002X)
R515  ValueDisplayed: 4.99k  [0402L]  (hidden comment: CRCW04024K99FKED)
R516  ValueDisplayed: 100  [0603L]  (hidden comment: CRCW0603100RFKEA)
R517  ValueDisplayed: 4.99k  [0402L]  (hidden comment: CRCW04024K99FKED)
R518  ValueDisplayed: 3.3  [0603L]  (hidden comment: CRCW06033R30JNEA)
R519  ValueDisplayed: 22.0k  [0603L]  (hidden comment: RC0603FR-0722KL)
R520  ValueDisplayed: 3.3  [0603L]  (hidden comment: CRCW06033R30JNEA)
U500  PCM5252RHBR  [RHB0032E]
U501  TPA3244DDWR  [DDW0044D_N]

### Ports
BCK5 (in), DIN2 (in), INA5 (in), INB5 (in), INC5 (in), IND5 (in), LRCK5 (in), OSC-IOM (in), OSC-IOP (in), SCK5 (in), SCL5 (in), SDA5 (bidir), ~{AMP-RESET5} (in), ~{CLIP_OTW5} (out), ~{FAULT5} (out)

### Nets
3.3V-2: C506.1 C507.1 C508.1 C509.1 R500.1 R510.2 R511.2 R512.1 R517.2 U500.4(DVDD) U500.5(CPVDD)
12V: C501.1 C524.1 L500.1 U501.1(GVDD_CD) U501.22(GVDD_AB)
GND: C500.2(-) C501.2 C502.1 C503.1 C504.2 C505.2 C506.2 C507.2 C508.2 C509.2 C511.2(-) C512.2 C513.1 C514.1 C515.2 C518.2 C524.2 C525.2 C526.2 C528.2 C530.2 C531.2 C532.1 C533.1 C535.2 C537.2 C540.2 C542.1 C543.2 R504.1 R509.1 R513.1 R514.1 R515.2 R518.1 R519.1 R520.1 U500.3(DGND) U500.7(CPGND) U500.15(AGND) U500.33(GND) U501.10(GND) U501.11(GND) U501.19(M2) U501.20(M1) U501.25(GND) U501.26(GND) U501.33(GND) U501.34(GND) U501.41(GND) U501.42(GND) U501.45(PowerPAD)
PVDD: C500.1(+) C502.2 C503.2 C511.1(+) C513.2 C514.2 U501.29(PVDD_AB) U501.30(PVDD_AB) U501.31(PVDD_AB) U501.36(PVDD_CD) U501.37(PVDD_CD) U501.38(PVDD_CD)
~{AMP-RESET5}: U501.5(~{RESET}) ; port ~{AMP-RESET5}
~{CLIP_OTW5}: U501.2(~{CLIP_OTW}) ; port ~{CLIP_OTW5}
~{FAULT5}: U501.4(~{FAULT}) ; port ~{FAULT5}
BCK5: U500.27(BCK) ; port BCK5
CenterTweeter+: C515.1 C516.1 CT+.1 L501.2
CenterTweeter-: C526.1 C527.1 CT-.1 L501.3
CenterWoofer+: C535.1 C536.1 CW+.1 L502.2
CenterWoofer-: C540.1 C541.1 CW-.1 L502.3
DAC5L+: C517.1 JP500.1 R501.2
DAC5L-: C517.2 JP501.1 R503.2
DAC5R+: C521.2 JP502.1 R507.2
DAC5R-: C521.1 JP503.1 R505.2
DIN2: U500.28(DIN) ; port DIN2
DVDD5: C532.2 U501.12(DVDD) U501.15(FREQ_ADJ)
INA5: JP500.3 ; port INA5
INB5: JP501.3 ; port INB5
INC5: JP502.3 ; port INC5
IND5: JP503.3 ; port IND5
INPUTA5: C518.1 R502.2 U501.18(INPUT_A)
INPUTB5: C525.1 R506.2 U501.17(INPUT_B)
INPUTC5: C531.1 R508.2 U501.7(INPUT_C)
INPUTD5: C537.1 R516.2 U501.6(INPUT_D)
LRCK5: U500.31(LRCK) ; port LRCK5
OSC-IOM: U501.14(OSC_IOM) ; port OSC-IOM
OSC-IOP: U501.13(OSC_IOP) ; port OSC-IOP
OUT5A: C520.1 L501.1 U501.27(OUT_A) U501.28(OUT_A)
OUT5B: C523.1 L501.4 U501.32(OUT_B)
OUT5C: C538.1 L502.1 U501.35(OUT_C)
OUT5D: C539.1 L502.4 U501.39(OUT_D) U501.40(OUT_D)
OUTLN5: R503.1 U500.11(OUTLN)
OUTLP5: R501.1 U500.10(OUTLP)
OUTRN5: R505.1 U500.12(OUTRN)
OUTRP5: R507.1 U500.13(OUTRP)
SCK5: U500.26(SCK) ; port SCK5
SCL5: U500.18(MC/SCL/ATT1) ; port SCL5
SDA5: U500.17(MOSI/SDA/ATT2) ; port SDA5
VDD5: C512.1 L500.2 U501.21(VDD)
NetC504_1: C504.1 C505.1 R500.2 U500.14(AVDD)
NetC510_1: C510.1 JP500.2
NetC510_2: C510.2 R502.1
NetC516_2: C516.2 R504.2
NetC519_1: C519.1 JP501.2
NetC519_2: C519.2 R506.1
NetC520_2: C520.2 U501.23(BST_A)
NetC522_1: C522.1 U500.6(CAPP)
NetC522_2: C522.2 U500.8(CAPM)
NetC523_2: C523.2 U501.24(BST_B)
NetC527_2: C527.2 R509.2
NetC528_1: C528.1 U500.9(VNEG)
NetC529_1: C529.1 JP502.2
NetC529_2: C529.2 R508.1
NetC530_1: C530.1 U500.2(LDOO)
NetC533_2: C533.2 U501.9(AVDD)
NetC534_1: C534.1 JP503.2
NetC534_2: C534.2 R516.1
NetC536_2: C536.2 R518.2
NetC538_2: C538.2 U501.43(BST_C)
NetC539_2: C539.2 U501.44(BST_D)
NetC541_2: C541.2 R520.2
NetC542_2: C542.2 U501.3(VBG)
NetC543_1: C543.1 U501.8(C_START)
NetR510_1: R510.1 R513.2 U500.32(MISO(GPIO1)/ADR1/FMT)
NetR511_1: R511.1 R514.2 U500.22(GPIO2/ADR2/GPO)
NetR512_2: R512.2 U500.1(XSMT)
NetR515_1: R515.1 U500.23(MODE1)
NetR517_1: R517.1 U500.24(MS/MODE2)
NetR519_2: R519.2 U501.16(OC_ADJ)

Not connected (* = marked no-connect by the designer): U500 16(VCOM/DEMP) 19(GPIO5/ATT0) 20(GPIO4/MAST) 21(GPIO3/AGNS) 25(GPIO6/FLT) 29(NC) 30(NC)

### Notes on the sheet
- CENTER CHANNEL
- DUAL FP 1812/1206
- I2S
- ADDRESS
- SELECT
- (near U500) I2C-ADD=0x98
- I2C
- FROM
- INPUT HEADER
- MSP430
- TO MONITORS
- SURROUND CHANNEL

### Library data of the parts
C500 C511 = EEV-FK1H102M: as C200 on sheet TIDA-01414_UpChannel
C501 C512 C524 = C0603C104K5RACTU: as C201 on sheet TIDA-01414_UpChannel
C502 C503 C513 C514 = GRM31MR71H105KA88L: as C202 on sheet TIDA-01414_UpChannel
C504 C506 C508 = GRM188R61A106ME69D: as C204 on sheet TIDA-01414_UpChannel
C505 C507 C509 C530 = GRM155R71A104KA01D: as C205 on sheet TIDA-01414_UpChannel
C510 C519 C529 C534 = GRM31CR71C106KAC7L: as C210 on sheet TIDA-01414_UpChannel
C515 C526 C535 C540 = C3225X7R2A105K200AA: as C215 on sheet TIDA-01414_UpChannel
C516 C527 C536 C541 = C0603C103K5RACTU: as C216 on sheet TIDA-01414_UpChannel
C517 C521 = GRM1555C1H102JA01D: as C217 on sheet TIDA-01414_UpChannel
C518 C525 C531 C537 = GRM1885C1H101JA01D: as C218 on sheet TIDA-01414_UpChannel
C520 C523 C538 C539 = GRM188R71E333KA01D: as C220 on sheet TIDA-01414_UpChannel
C522 C528 = C1005X5R1A225K050BC: as C222 on sheet TIDA-01414_UpChannel
C532 C533 = GRM188R71C105KA12D: as C232 on sheet TIDA-01414_UpChannel
C542 = C0603C104K5RACTU: as C242 on sheet TIDA-01414_UpChannel
C543 = GRM188R71H473KA61D: as C243 on sheet TIDA-01414_UpChannel
CT+ CT- CW+ CW- = 63066-1: as UPL+ on sheet TIDA-01414_UpChannel
JP500-JP503 = SIP3-90_PBC03SAAN: as JP200-JP203 on sheet TIDA-01414_UpChannel
L500 = GLFR1608T100M-LR: as L200 on sheet TIDA-01414_UpChannel
L501 L502 = UA8014-ALD: as L201 on sheet TIDA-01414_UpChannel
R500 = CRCW060310R0JNEA: as R200 on sheet TIDA-01414_UpChannel
R501 R503 R505 R507 = CRCW0603499RFKEA: as R201 on sheet TIDA-01414_UpChannel
R502 R506 R508 R516 = CRCW0603100RFKEA: as R202 on sheet TIDA-01414_UpChannel
R504 R509 R518 R520 = CRCW06033R30JNEA: as R204 on sheet TIDA-01414_UpChannel
R510-R514 = ERJ-2RKF1002X: as R210-R214 on sheet TIDA-01414_UpChannel
R515 R517 = CRCW04024K99FKED: as R215 on sheet TIDA-01414_UpChannel
R519 = RC0603FR-0722KL: as R219 on sheet TIDA-01414_UpChannel
U500 = PCM5252RHBR: as U200 on sheet TIDA-01414_UpChannel
U501 = TPA3244DDWR: as U201 on sheet TIDA-01414_UpChannel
